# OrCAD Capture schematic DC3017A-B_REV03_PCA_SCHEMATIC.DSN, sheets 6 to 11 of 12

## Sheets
6 PORTS 9-12: size Custom
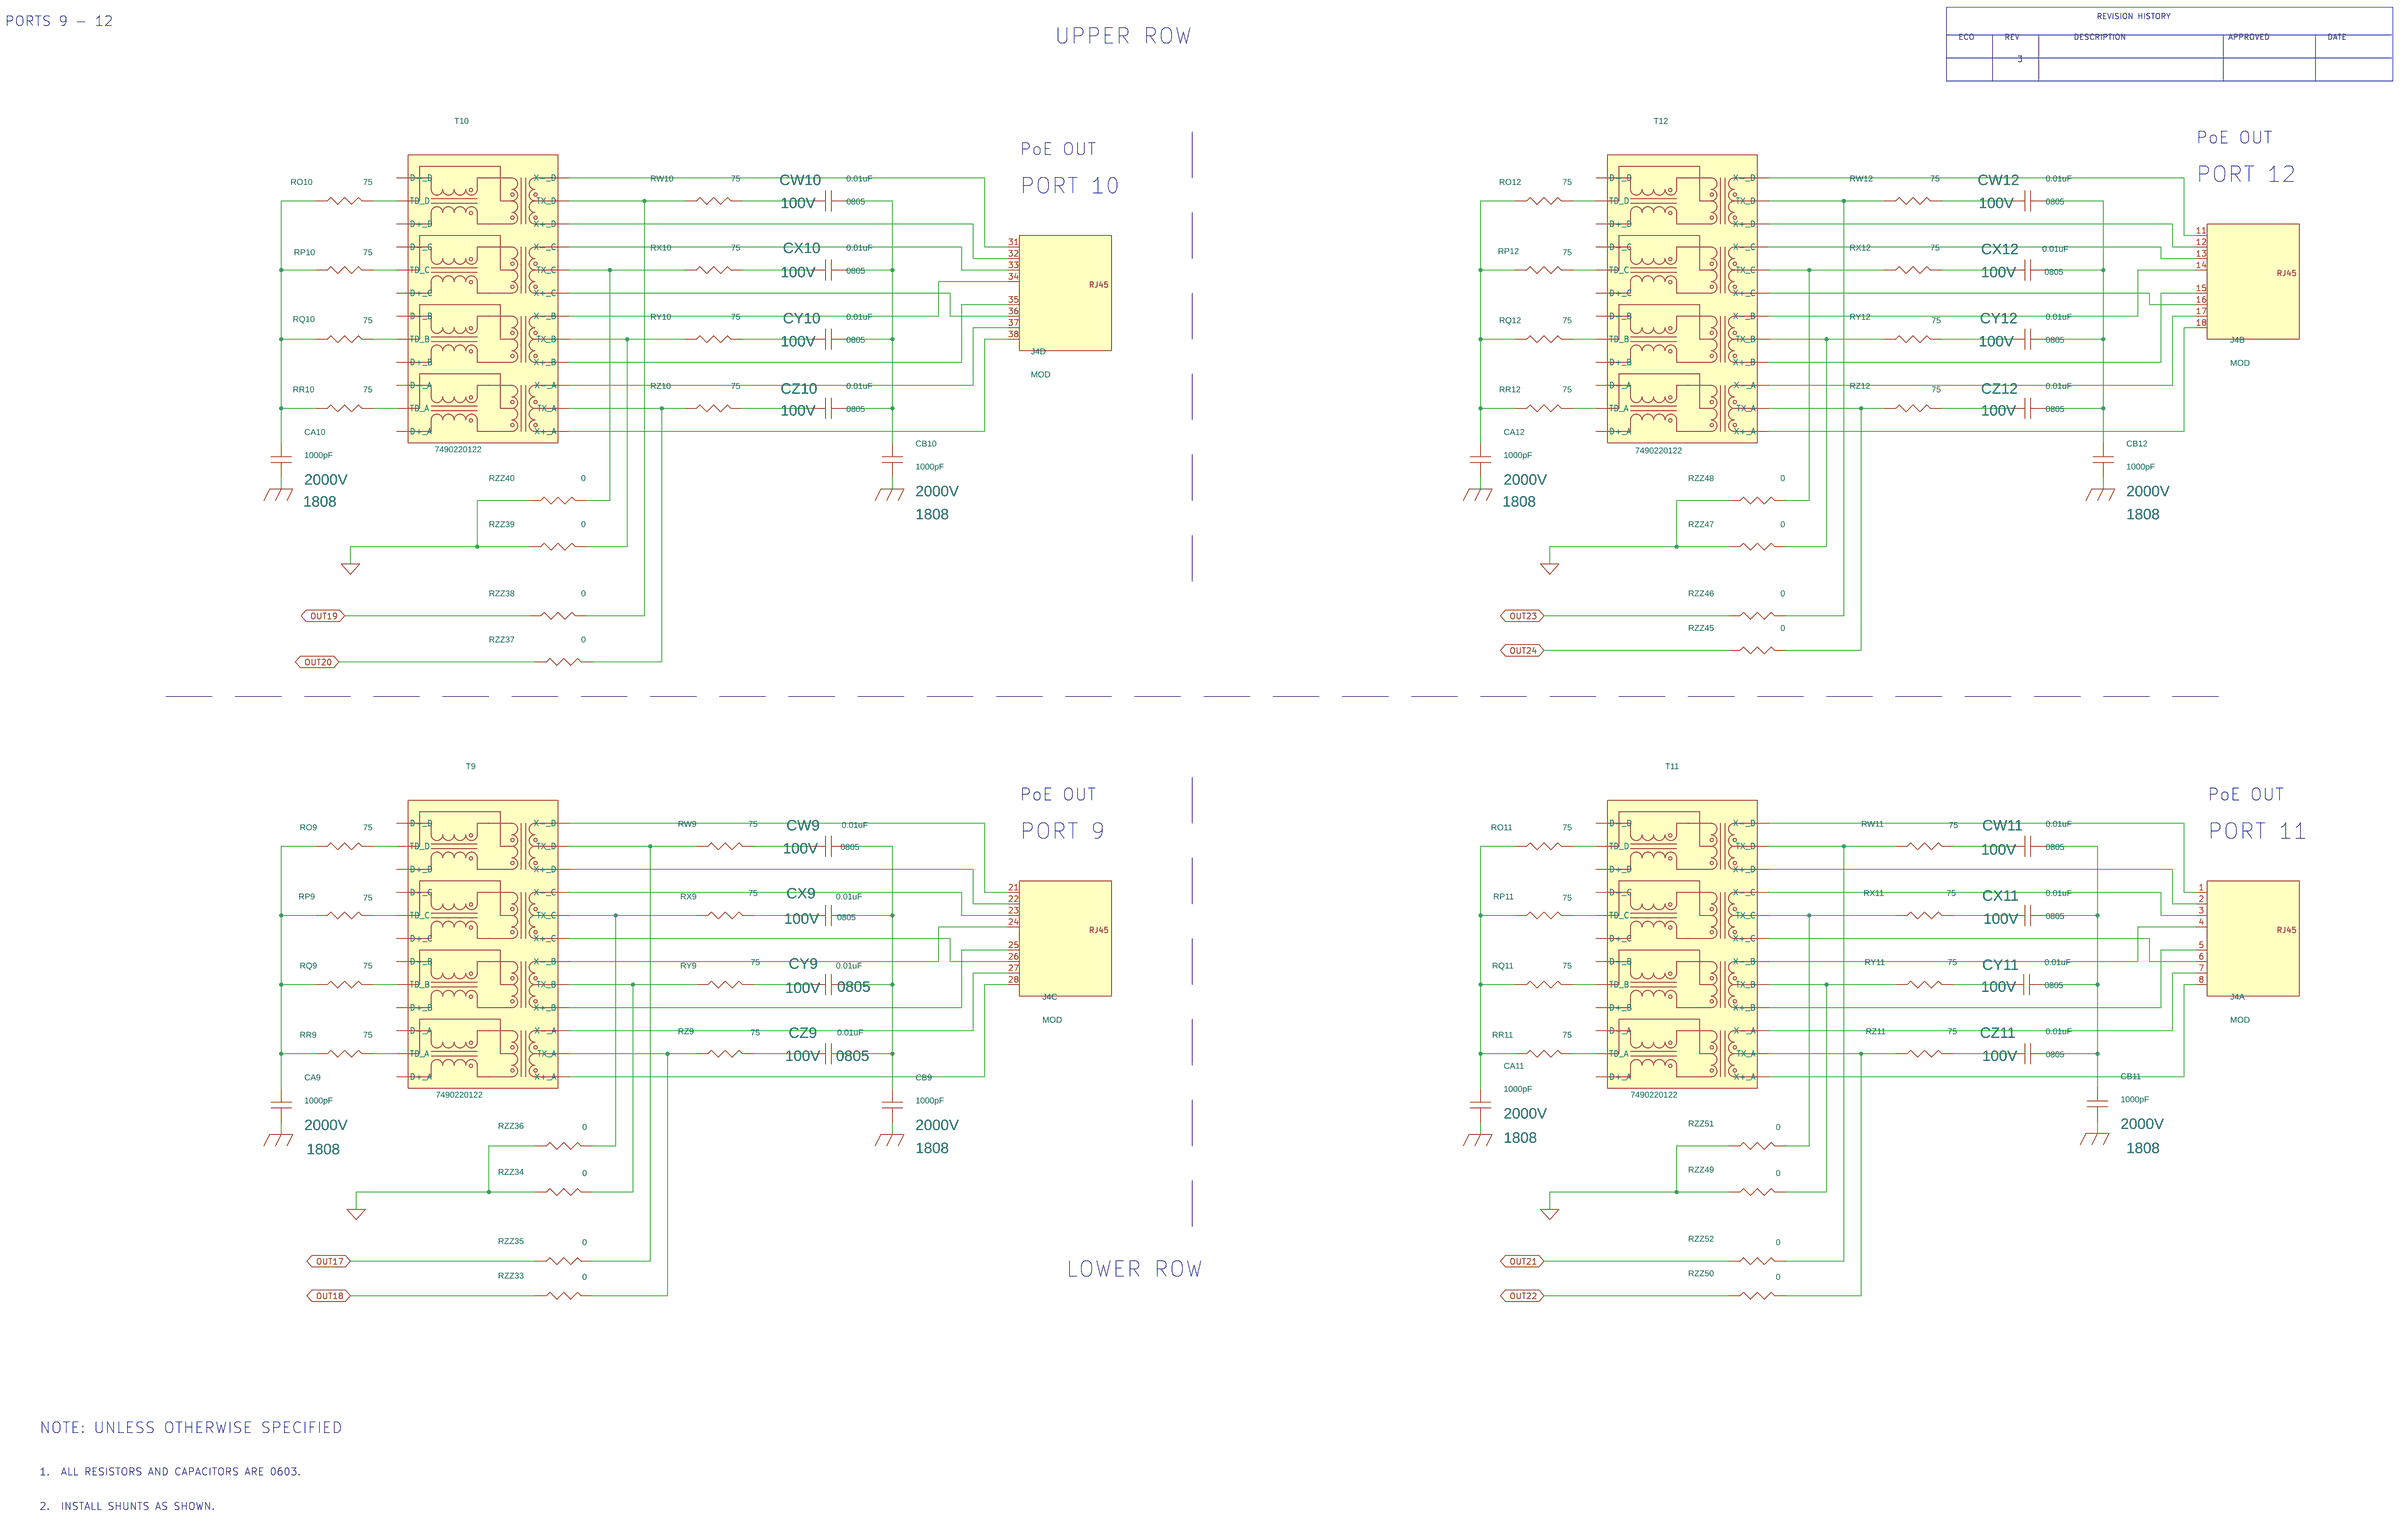
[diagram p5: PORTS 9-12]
7 PORTS 13-16: size Custom
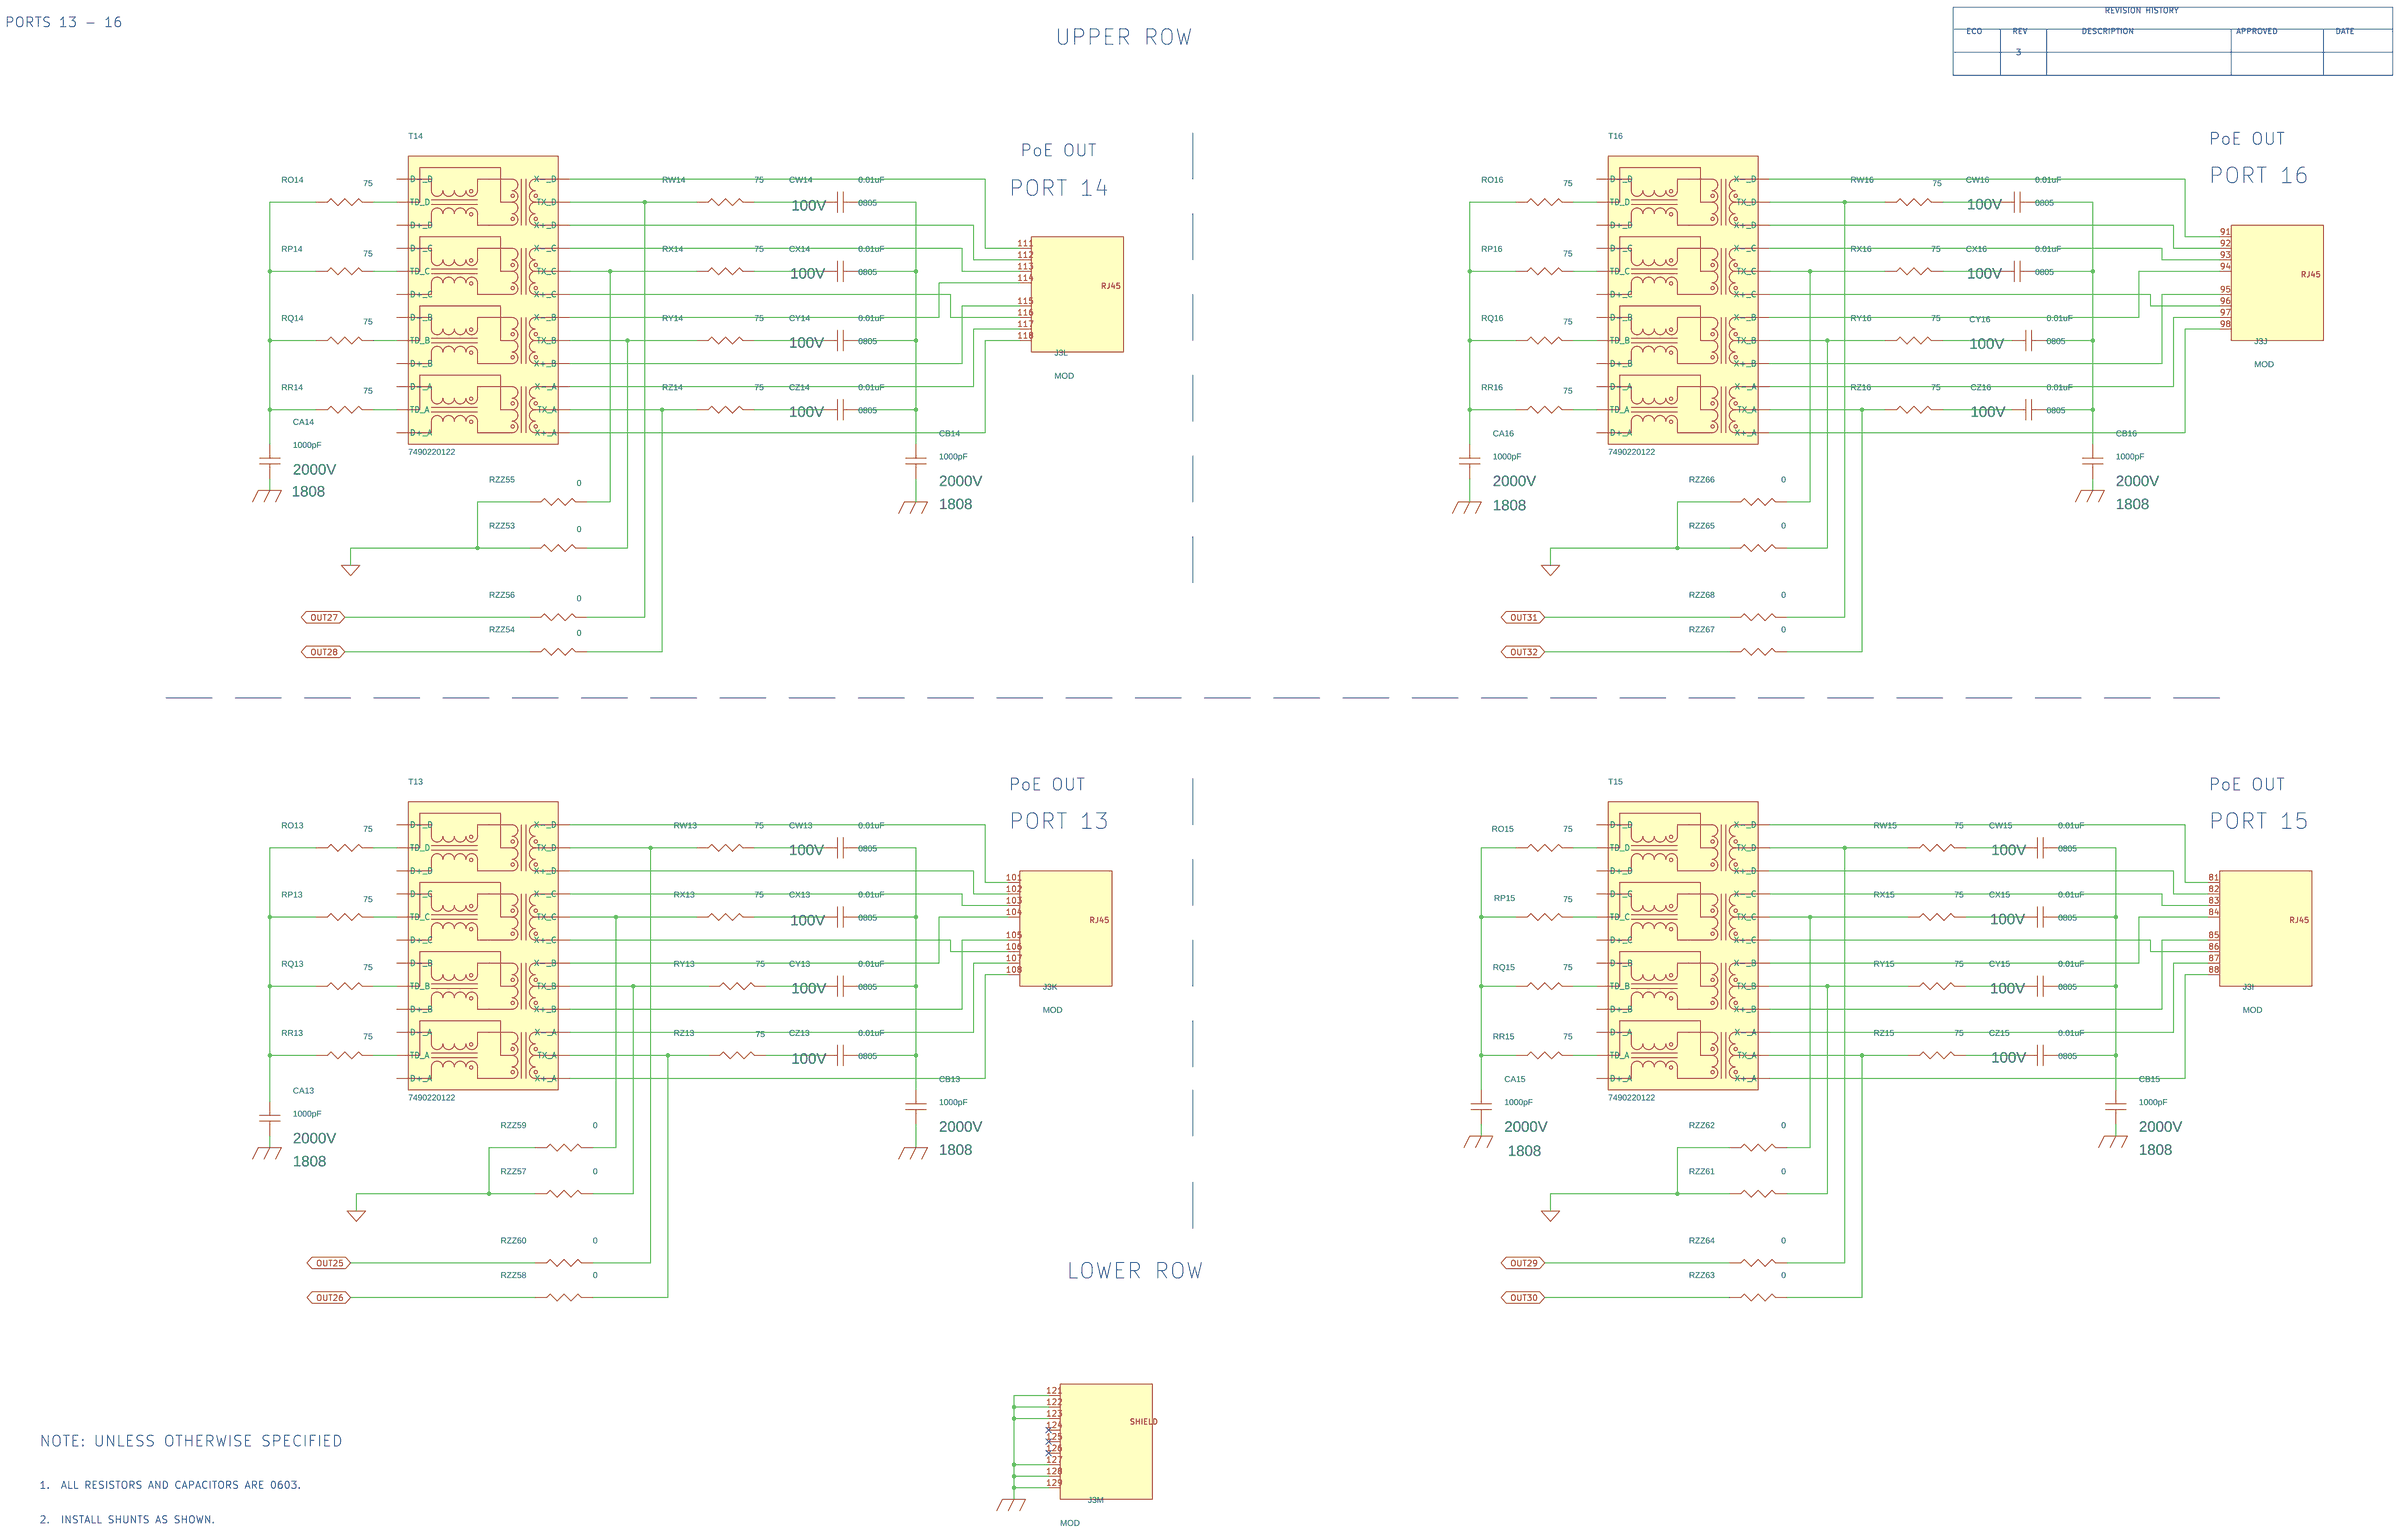
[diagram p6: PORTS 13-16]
8 PORTS 17-20: size Custom
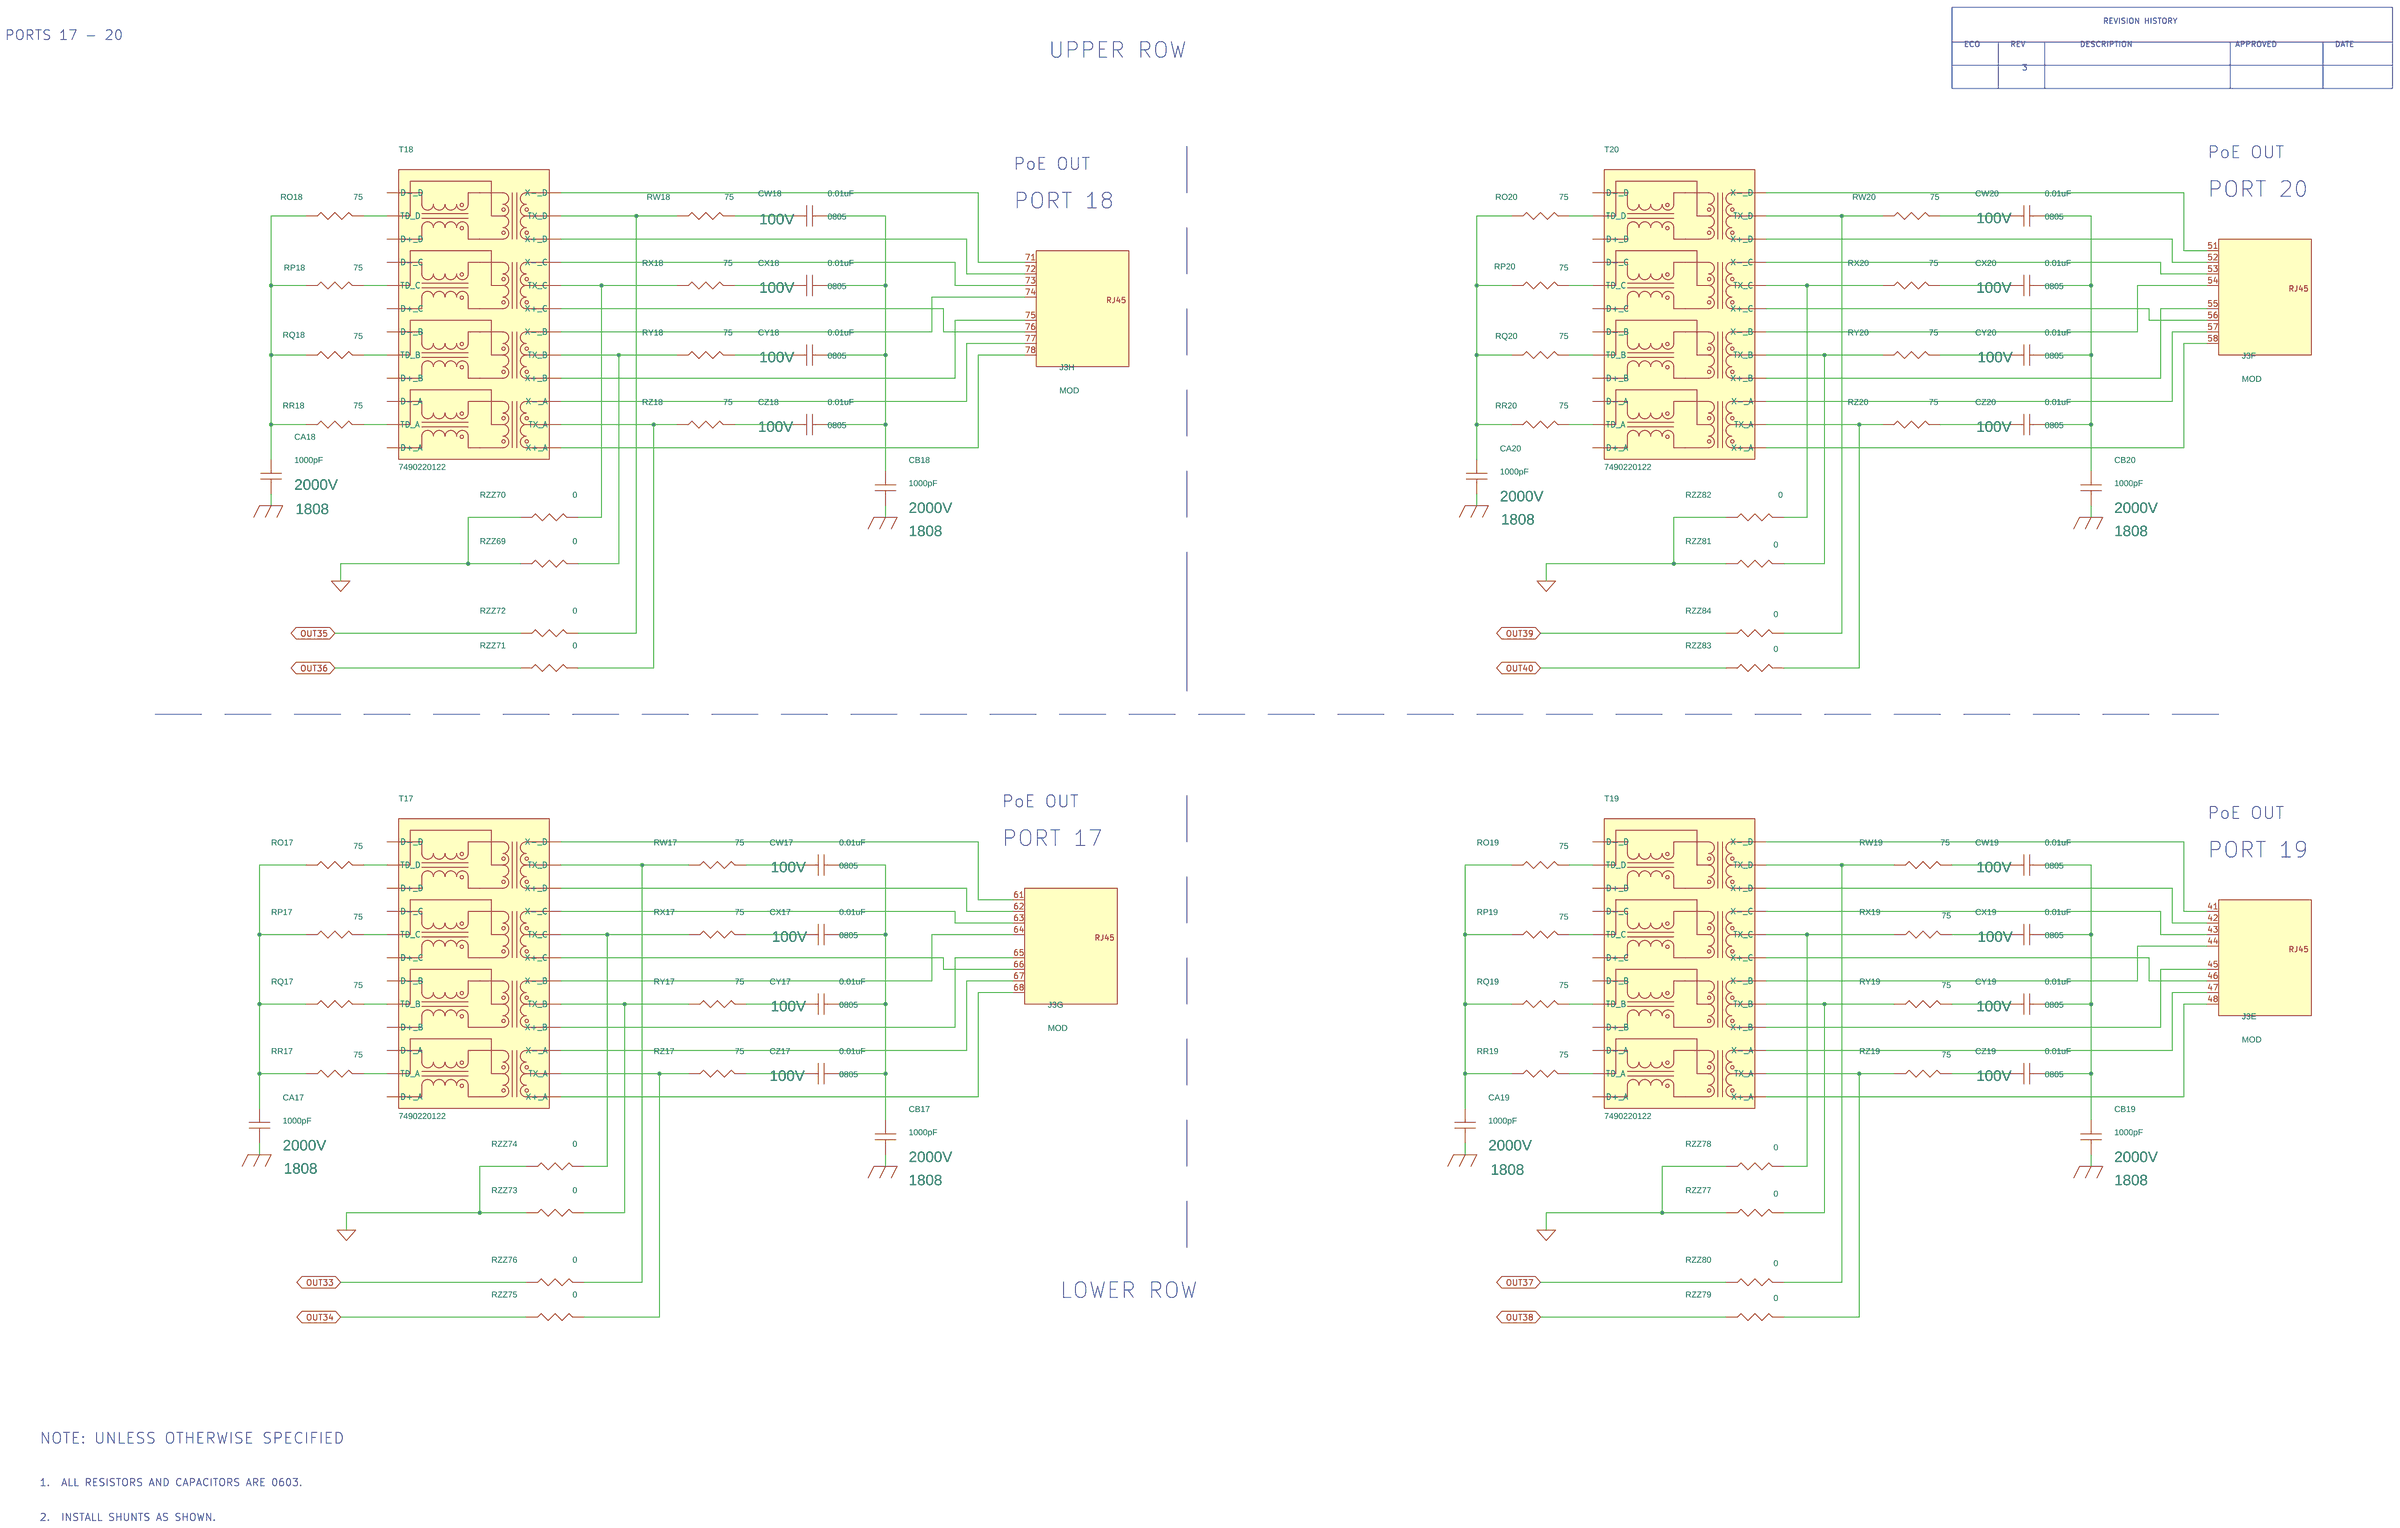
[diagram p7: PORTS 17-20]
9 PORTS 21-24: size Custom
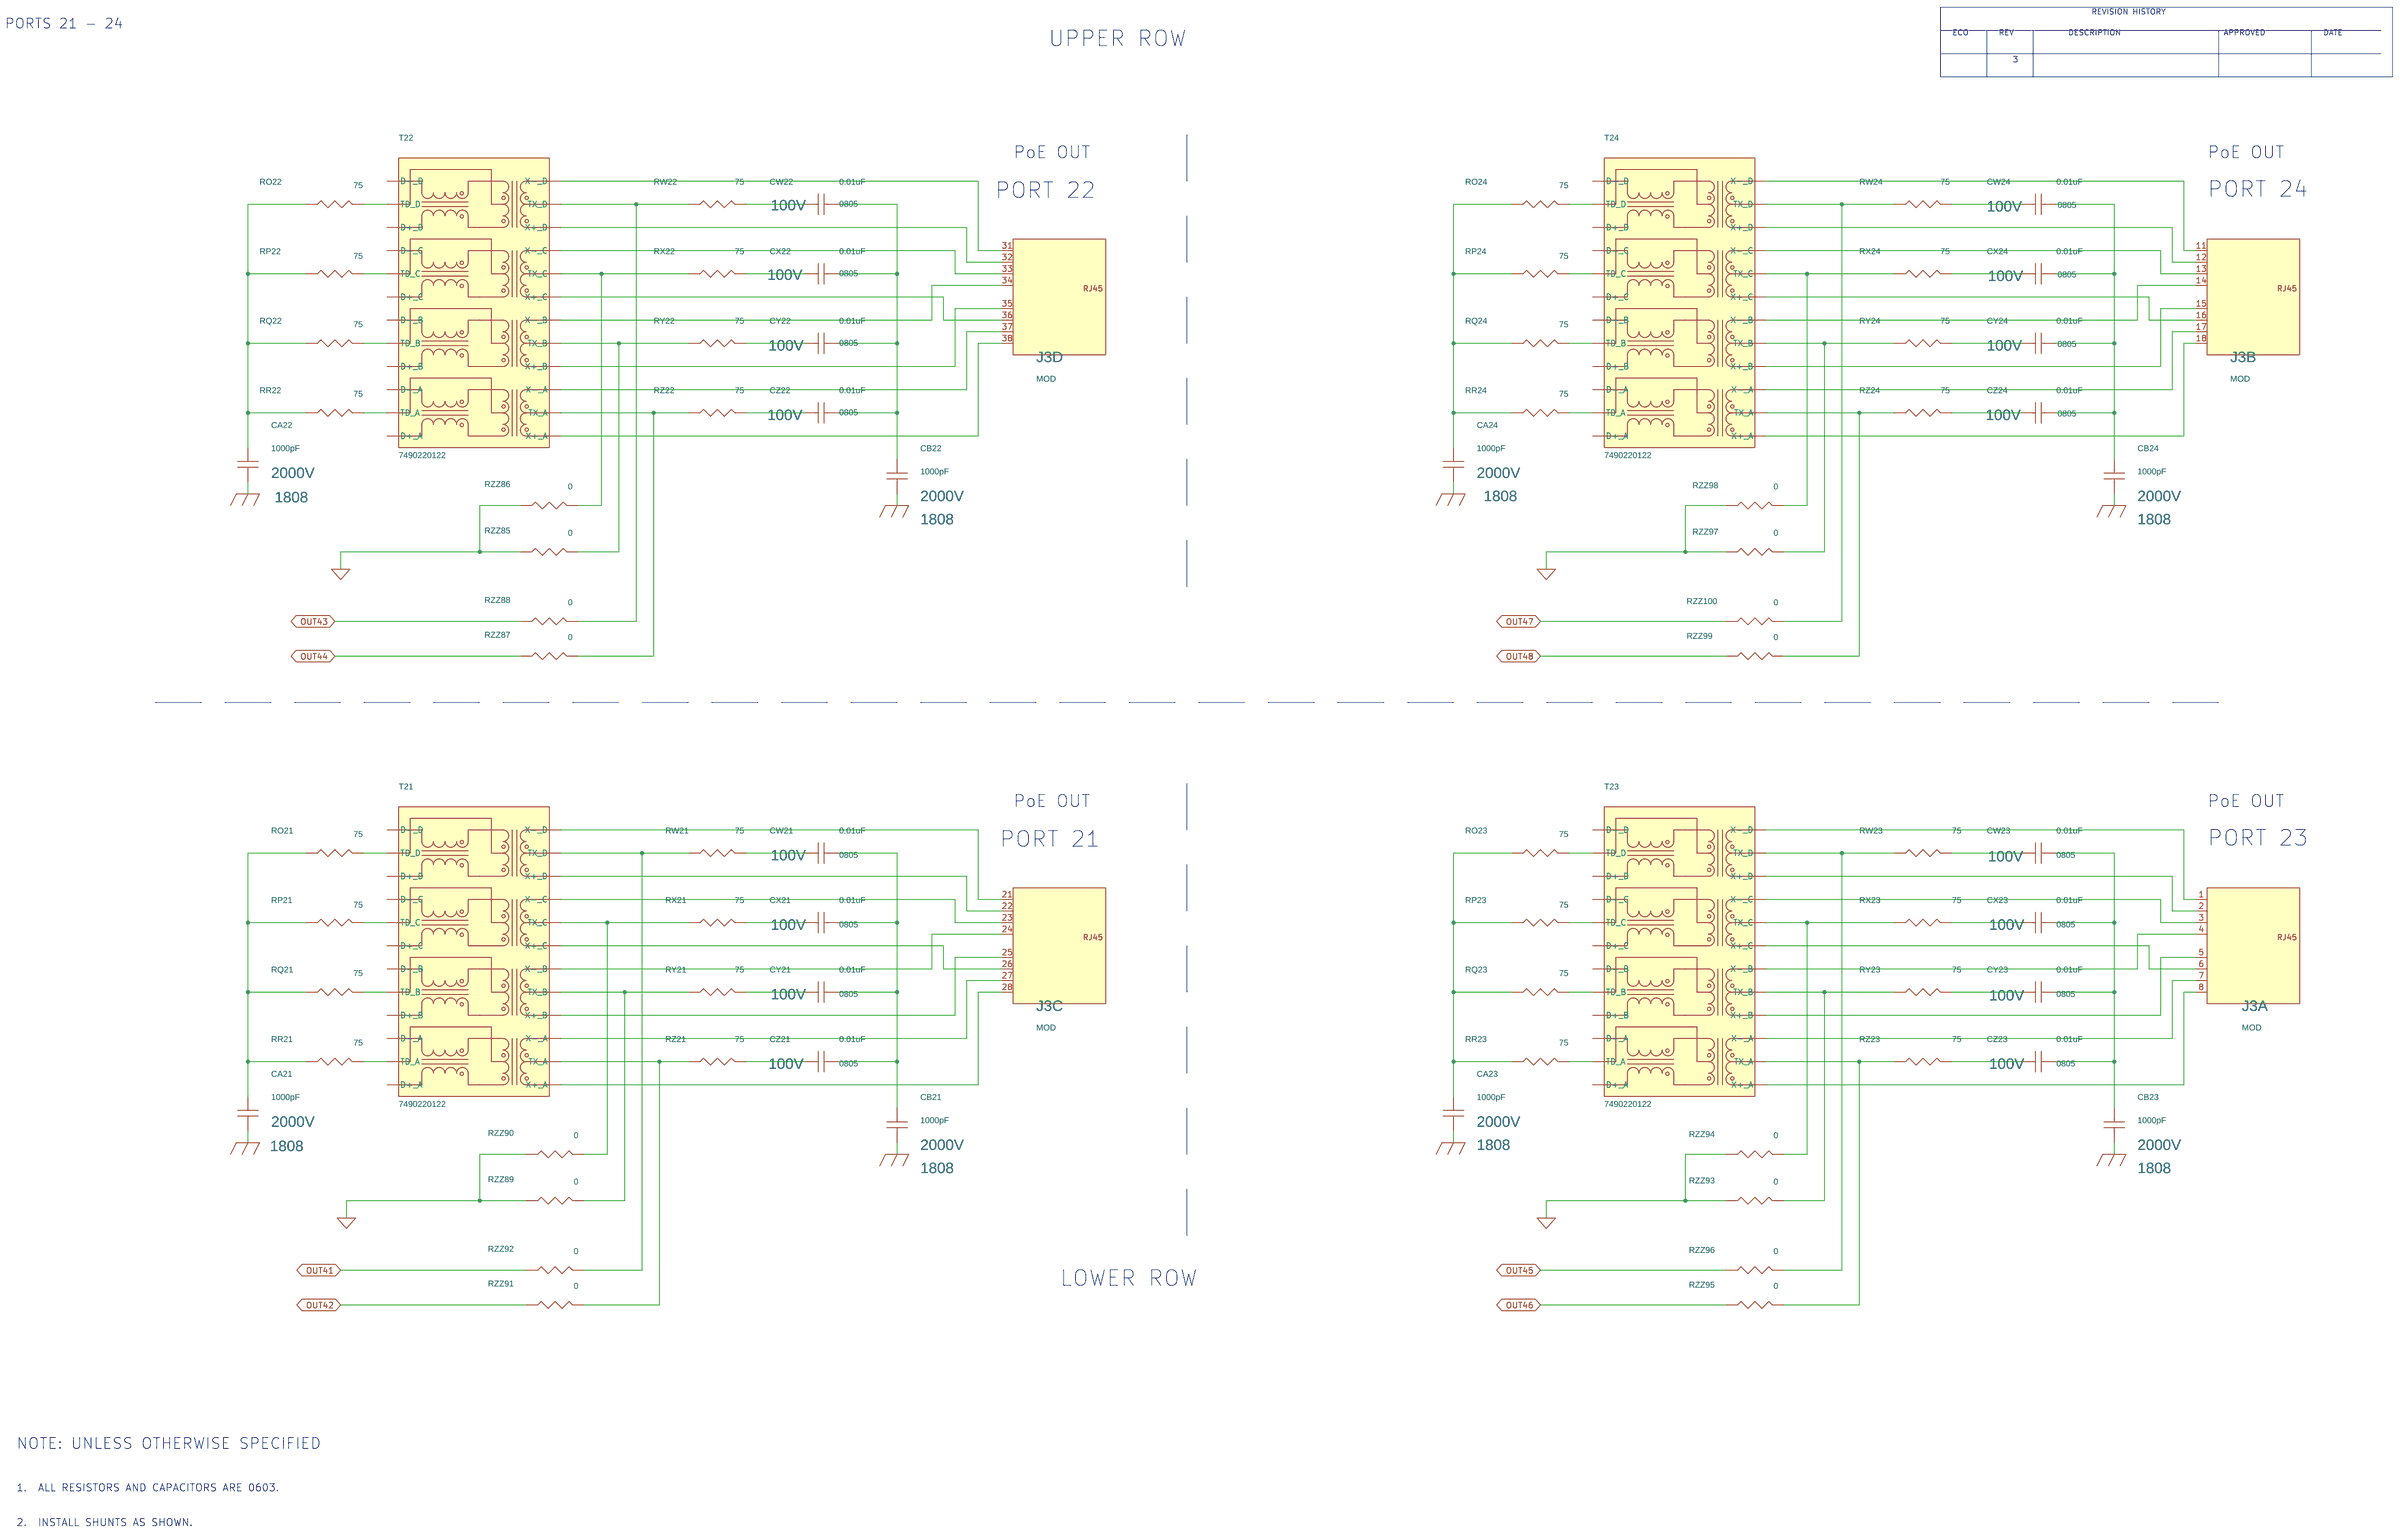
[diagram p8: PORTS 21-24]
10 _12-HARDWARE
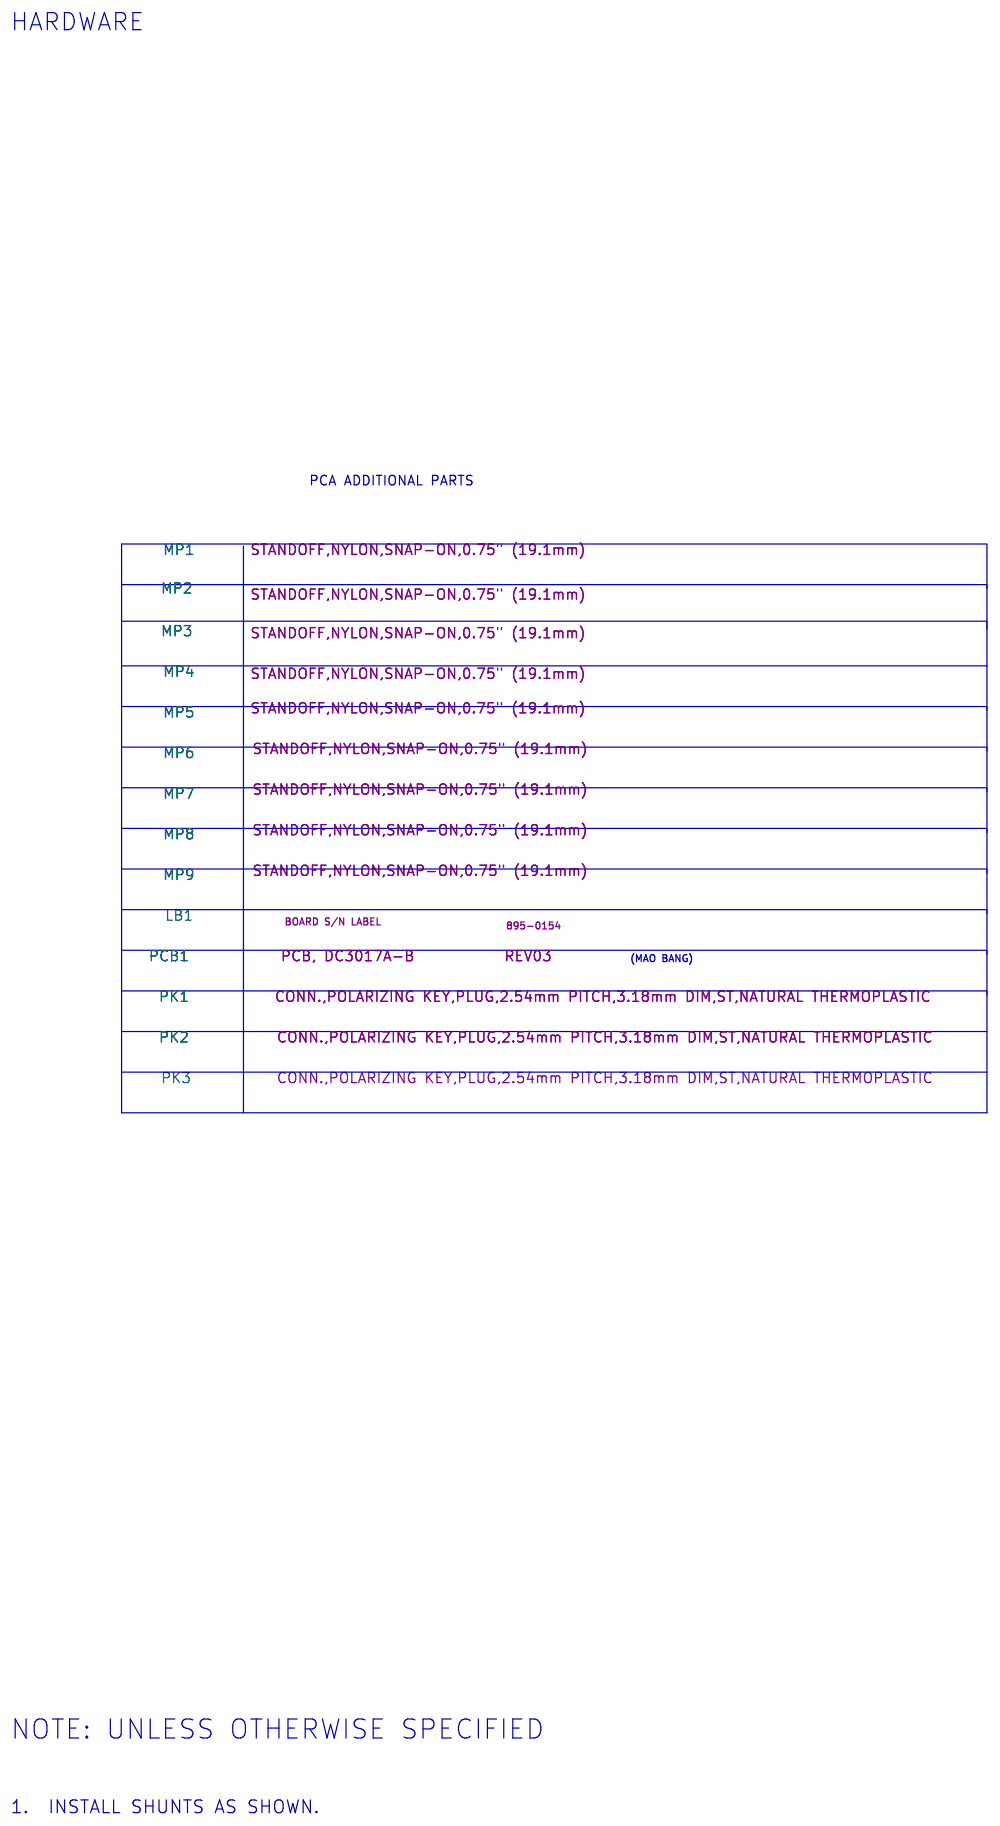
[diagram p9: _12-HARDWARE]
11 _11-PORTS 13-24 LEDS: size Custom
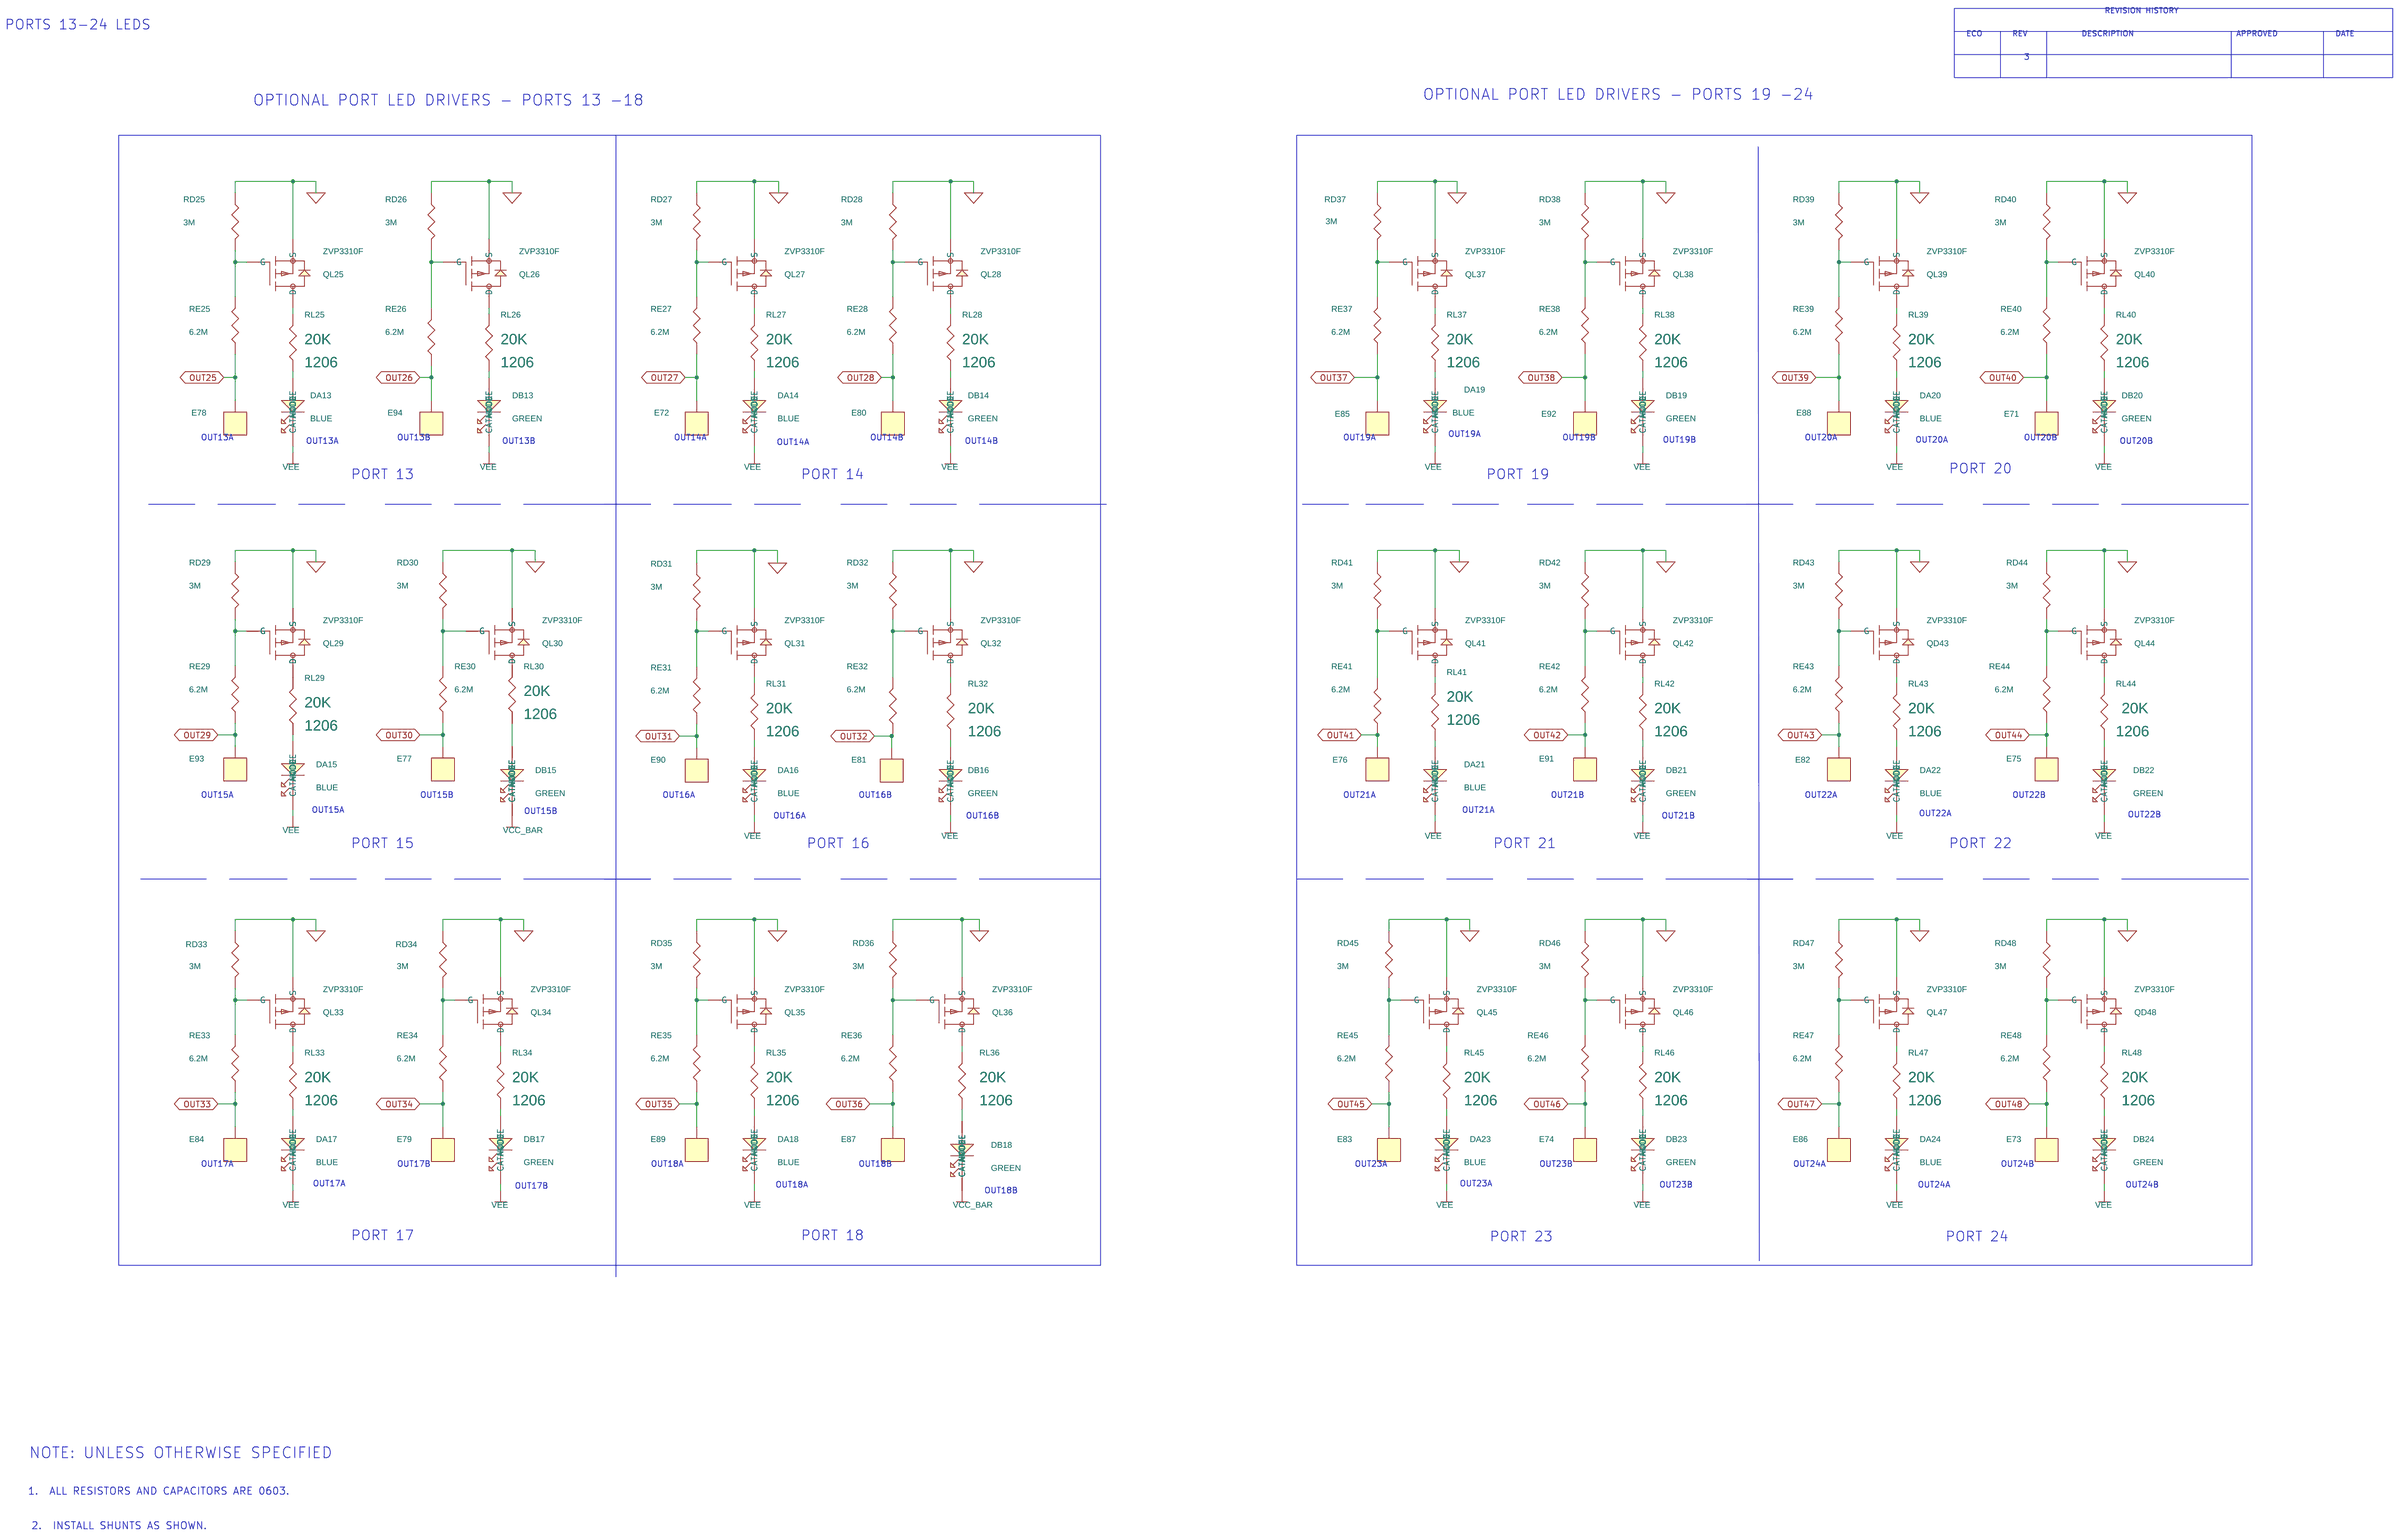
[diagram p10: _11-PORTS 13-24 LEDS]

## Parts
sheet _11-PORTS 13-24 LEDS
DA13  BLUE  [LED_0603]
DA14  BLUE  [LED_0603]
DA15  BLUE  [LED_0603]
DA16  BLUE  [LED_0603]
DA17  BLUE  [LED_0603]
DA18  BLUE  [LED_0603]
DA19  BLUE  [LED_0603]
DA20  BLUE  [LED_0603]
DA21  BLUE  [LED_0603]
DA22  BLUE  [LED_0603]
DA23  BLUE  [LED_0603]
DA24  BLUE  [LED_0603]
DB13  GREEN  [LED_0603]
DB14  GREEN  [LED_0603]
DB15  GREEN  [LED_0603]
DB16  GREEN  [LED_0603]
DB17  GREEN  [LED_0603]
DB18  GREEN  [LED_0603]
DB19  GREEN  [LED_0603]
DB20  GREEN  [LED_0603]
DB21  GREEN  [LED_0603]
DB22  GREEN  [LED_0603]
DB23  GREEN  [LED_0603]
DB24  GREEN  [LED_0603]
E71  TEST POINT  [KEYSTONE_5019]
E72  TEST POINT  [KEYSTONE_5019]
E73  TEST POINT  [KEYSTONE_5019]
E74  TEST POINT  [KEYSTONE_5019]
E75  TEST POINT  [KEYSTONE_5019]
E76  TEST POINT  [KEYSTONE_5019]
E77  TEST POINT  [KEYSTONE_5019]
E78  TEST POINT  [KEYSTONE_5019]
E79  TEST POINT  [KEYSTONE_5019]
E80  TEST POINT  [KEYSTONE_5019]
E81  TEST POINT  [KEYSTONE_5019]
E82  TEST POINT  [KEYSTONE_5019]
E83  TEST POINT  [KEYSTONE_5019]
E84  TEST POINT  [KEYSTONE_5019]
E85  TEST POINT  [KEYSTONE_5019]
E86  TEST POINT  [KEYSTONE_5019]
E87  TEST POINT  [KEYSTONE_5019]
E88  TEST POINT  [KEYSTONE_5019]
E89  TEST POINT  [KEYSTONE_5019]
E90  TEST POINT  [KEYSTONE_5019]
E91  TEST POINT  [KEYSTONE_5019]
E92  TEST POINT  [KEYSTONE_5019]
E93  TEST POINT  [KEYSTONE_5019]
E94  TEST POINT  [KEYSTONE_5019]
QD43  ZVP3310F  [SOT23-3N]
QD48  ZVP3310F  [SOT23-3N]
QL25  ZVP3310F  [SOT23-3N]
QL26  ZVP3310F  [SOT23-3N]
QL27  ZVP3310F  [SOT23-3N]
QL28  ZVP3310F  [SOT23-3N]
QL29  ZVP3310F  [SOT23-3N]
QL30  ZVP3310F  [SOT23-3N]
QL31  ZVP3310F  [SOT23-3N]
QL32  ZVP3310F  [SOT23-3N]
QL33  ZVP3310F  [SOT23-3N]
QL34  ZVP3310F  [SOT23-3N]
QL35  ZVP3310F  [SOT23-3N]
QL36  ZVP3310F  [SOT23-3N]
QL37  ZVP3310F  [SOT23-3N]
QL38  ZVP3310F  [SOT23-3N]
QL39  ZVP3310F  [SOT23-3N]
QL40  ZVP3310F  [SOT23-3N]
QL41  ZVP3310F  [SOT23-3N]
QL42  ZVP3310F  [SOT23-3N]
QL44  ZVP3310F  [SOT23-3N]
QL45  ZVP3310F  [SOT23-3N]
QL46  ZVP3310F  [SOT23-3N]
QL47  ZVP3310F  [SOT23-3N]
RD25  3M  [CR0603N]
RD26  3M  [CR0603N]
RD27  3M  [CR0603N]
RD28  3M  [CR0603N]
RD29  3M  [CR0603N]
RD30  3M  [CR0603N]
RD31  3M  [CR0603N]
RD32  3M  [CR0603N]
RD33  3M  [CR0603N]
RD34  3M  [CR0603N]
RD35  3M  [CR0603N]
RD36  3M  [CR0603N]
RD37  3M  [CR0603N]
RD38  3M  [CR0603N]
RD39  3M  [CR0603N]
RD40  3M  [CR0603N]
RD41  3M  [CR0603N]
RD42  3M  [CR0603N]
RD43  3M  [CR0603N]
RD44  3M  [CR0603N]
RD45  3M  [CR0603N]
RD46  3M  [CR0603N]
RD47  3M  [CR0603N]
RD48  3M  [CR0603N]
RE25  6.2M  [CR0603N]
RE26  6.2M  [CR0603N]
RE27  6.2M  [CR0603N]
RE28  6.2M  [CR0603N]
RE29  6.2M  [CR0603N]
RE30  6.2M  [CR0603N]
RE31  6.2M  [CR0603N]
RE32  6.2M  [CR0603N]
RE33  6.2M  [CR0603N]
RE34  6.2M  [CR0603N]
RE35  6.2M  [CR0603N]
RE36  6.2M  [CR0603N]
RE37  6.2M  [CR0603N]
RE38  6.2M  [CR0603N]
RE39  6.2M  [CR0603N]
RE40  6.2M  [CR0603N]
RE41  6.2M  [CR0603N]
RE42  6.2M  [CR0603N]
RE43  6.2M  [CR0603N]
RE44  6.2M  [CR0603N]
RE45  6.2M  [CR0603N]
RE46  6.2M  [CR0603N]
RE47  6.2M  [CR0603N]
RE48  6.2M  [CR0603N]
RL25  20K  [CR1206N]
RL26  20K  [CR1206N]
RL27  20K  [CR1206N]
RL28  20K  [CR1206N]
RL29  20K  [CR1206N]
RL30  20K  [CR1206N]
RL31  20K  [CR1206N]
RL32  20K  [CR1206N]
RL33  20K  [CR1206N]
RL34  20K  [CR1206N]
RL35  20K  [CR1206N]
RL36  20K  [CR1206N]
RL37  20K  [CR1206N]
RL38  20K  [CR1206N]
RL39  20K  [CR1206N]
RL40  20K  [CR1206N]
RL41  20K  [CR1206N]
RL42  20K  [CR1206N]
RL43  20K  [CR1206N]
RL44  20K  [CR1206N]
RL45  20K  [CR1206N]
RL46  20K  [CR1206N]
RL47  20K  [CR1206N]
RL48  20K  [CR1206N]
sheet _12-HARDWARE
LB1  LABEL  [895-0154_REV01]
MP1  STANDOFF  [KEYSTONE_8829-8834]
MP2  STANDOFF  [KEYSTONE_8829-8834]
MP3  STANDOFF  [KEYSTONE_8829-8834]
MP4  STANDOFF  [KEYSTONE_8829-8834]
MP5  STANDOFF  [KEYSTONE_8829-8834]
MP6  STANDOFF  [KEYSTONE_8829-8834]
MP7  STANDOFF  [KEYSTONE_8829-8834]
MP8  STANDOFF  [KEYSTONE_8829-8834]
MP9  STANDOFF  [KEYSTONE_8829-8834]
PCB1  PCB, DC3017A-B
PK1  POLARIZING KEY  [SAMTEC-PK-01-07]
PK2  POLARIZING KEY  [SAMTEC-PK-01-07]
PK3  POLARIZING KEY  [SAMTEC-PK-01-07]
sheet PORTS 1-4
J4  MOD  [STEWART-SS73100-046F]  (sections A,B,C,D,E,F,G,H,I,J,K,L,M)
sheet PORTS 9-12
CA9  1000pF  [CC1808N]
CA10  1000pF  [CC1808N]
CA11  1000pF  [CC1808N]
CA12  1000pF  [CC1808N]
CB9  1000pF  [CC1808N]
CB10  1000pF  [CC1808N]
CB11  1000pF  [CC1808N]
CB12  1000pF  [CC1808N]
CW9  0.01uF  [CC0805N]
CW10  0.01uF  [CC0805N]
CW11  0.01uF  [CC0805N]
CW12  0.01uF  [CC0805N]
CX9  0.01uF  [CC0805N]
CX10  0.01uF  [CC0805N]
CX11  0.01uF  [CC0805N]
CX12  0.01uF  [CC0805N]
CY9  0.01uF  [CC0805N]
CY10  0.01uF  [CC0805N]
CY11  0.01uF  [CC0805N]
CY12  0.01uF  [CC0805N]
CZ9  0.01uF  [CC0805N]
CZ10  0.01uF  [CC0805N]
CZ11  0.01uF  [CC0805N]
CZ12  0.01uF  [CC0805N]
RO9  75  [CR0603N]
RO10  75  [CR0603N]
RO11  75  [CR0603N]
RO12  75  [CR0603N]
RP9  75  [CR0603N]
RP10  75  [CR0603N]
RP11  75  [CR0603N]
RP12  75  [CR0603N]
RQ9  75  [CR0603N]
RQ10  75  [CR0603N]
RQ11  75  [CR0603N]
RQ12  75  [CR0603N]
RR9  75  [CR0603N]
RR10  75  [CR0603N]
RR11  75  [CR0603N]
RR12  75  [CR0603N]
RW9  75  [CR0603N]
RW10  75  [CR0603N]
RW11  75  [CR0603N]
RW12  75  [CR0603N]
RX9  75  [CR0603N]
RX10  75  [CR0603N]
RX11  75  [CR0603N]
RX12  75  [CR0603N]
RY9  75  [CR0603N]
RY10  75  [CR0603N]
RY11  75  [CR0603N]
RY12  75  [CR0603N]
RZ9  75  [CR0603N]
RZ10  75  [CR0603N]
RZ11  75  [CR0603N]
RZ12  75  [CR0603N]
RZZ33  0  [CR0603N]
RZZ34  0  [CR0603N]
RZZ35  0  [CR0603N]
RZZ36  0  [CR0603N]
RZZ37  0  [CR0603N]
RZZ38  0  [CR0603N]
RZZ39  0  [CR0603N]
RZZ40  0  [CR0603N]
RZZ45  0  [CR0603N]
RZZ46  0  [CR0603N]
RZZ47  0  [CR0603N]
RZZ48  0  [CR0603N]
RZZ49  0  [CR0603N]
RZZ50  0  [CR0603N]
RZZ51  0  [CR0603N]
RZZ52  0  [CR0603N]
T9  7490220122  [WURTH-7490220122]
T10  7490220122  [WURTH-7490220122]
T11  7490220122  [WURTH-7490220122]
T12  7490220122  [WURTH-7490220122]
sheet PORTS 13-16
CA13  1000pF  [CC1808N]
CA14  1000pF  [CC1808N]
CA15  1000pF  [CC1808N]
CA16  1000pF  [CC1808N]
CB13  1000pF  [CC1808N]
CB14  1000pF  [CC1808N]
CB15  1000pF  [CC1808N]
CB16  1000pF  [CC1808N]
CW13  0.01uF  [CC0805N]
CW14  0.01uF  [CC0805N]
CW15  0.01uF  [CC0805N]
CW16  0.01uF  [CC0805N]
CX13  0.01uF  [CC0805N]
CX14  0.01uF  [CC0805N]
CX15  0.01uF  [CC0805N]
CX16  0.01uF  [CC0805N]
CY13  0.01uF  [CC0805N]
CY14  0.01uF  [CC0805N]
CY15  0.01uF  [CC0805N]
CY16  0.01uF  [CC0805N]
CZ13  0.01uF  [CC0805N]
CZ14  0.01uF  [CC0805N]
CZ15  0.01uF  [CC0805N]
CZ16  0.01uF  [CC0805N]
RO13  75  [CR0603N]
RO14  75  [CR0603N]
RO15  75  [CR0603N]
RO16  75  [CR0603N]
RP13  75  [CR0603N]
RP14  75  [CR0603N]
RP15  75  [CR0603N]
RP16  75  [CR0603N]
RQ13  75  [CR0603N]
RQ14  75  [CR0603N]
RQ15  75  [CR0603N]
RQ16  75  [CR0603N]
RR13  75  [CR0603N]
RR14  75  [CR0603N]
RR15  75  [CR0603N]
RR16  75  [CR0603N]
RW13  75  [CR0603N]
RW14  75  [CR0603N]
RW15  75  [CR0603N]
RW16  75  [CR0603N]
RX13  75  [CR0603N]
RX14  75  [CR0603N]
RX15  75  [CR0603N]
RX16  75  [CR0603N]
RY13  75  [CR0603N]
RY14  75  [CR0603N]
RY15  75  [CR0603N]
RY16  75  [CR0603N]
RZ13  75  [CR0603N]
RZ14  75  [CR0603N]
RZ15  75  [CR0603N]
RZ16  75  [CR0603N]
RZZ53  0  [CR0603N]
RZZ54  0  [CR0603N]
RZZ55  0  [CR0603N]
RZZ56  0  [CR0603N]
RZZ57  0  [CR0603N]
RZZ58  0  [CR0603N]
RZZ59  0  [CR0603N]
RZZ60  0  [CR0603N]
RZZ61  0  [CR0603N]
RZZ62  0  [CR0603N]
RZZ63  0  [CR0603N]
RZZ64  0  [CR0603N]
RZZ65  0  [CR0603N]
RZZ66  0  [CR0603N]
RZZ67  0  [CR0603N]
RZZ68  0  [CR0603N]
T13  7490220122  [WURTH-7490220122]
T14  7490220122  [WURTH-7490220122]
T15  7490220122  [WURTH-7490220122]
T16  7490220122  [WURTH-7490220122]
sheet PORTS 17-20
CA17  1000pF  [CC1808N]
CA18  1000pF  [CC1808N]
CA19  1000pF  [CC1808N]
CA20  1000pF  [CC1808N]
CB17  1000pF  [CC1808N]
CB18  1000pF  [CC1808N]
CB19  1000pF  [CC1808N]
CB20  1000pF  [CC1808N]
CW17  0.01uF  [CC0805N]
CW18  0.01uF  [CC0805N]
CW19  0.01uF  [CC0805N]
CW20  0.01uF  [CC0805N]
CX17  0.01uF  [CC0805N]
CX18  0.01uF  [CC0805N]
CX19  0.01uF  [CC0805N]
CX20  0.01uF  [CC0805N]
CY17  0.01uF  [CC0805N]
CY18  0.01uF  [CC0805N]
CY19  0.01uF  [CC0805N]
CY20  0.01uF  [CC0805N]
CZ17  0.01uF  [CC0805N]
CZ18  0.01uF  [CC0805N]
CZ19  0.01uF  [CC0805N]
CZ20  0.01uF  [CC0805N]
J3  MOD  [STEWART-SS73100-046F]  (sections A,B,C,D,E,F,G,H,I,J,K,L,M)
RO17  75  [CR0603N]
RO18  75  [CR0603N]
RO19  75  [CR0603N]
RO20  75  [CR0603N]
RP17  75  [CR0603N]
RP18  75  [CR0603N]
RP19  75  [CR0603N]
RP20  75  [CR0603N]
RQ17  75  [CR0603N]
RQ18  75  [CR0603N]
RQ19  75  [CR0603N]
RQ20  75  [CR0603N]
RR17  75  [CR0603N]
RR18  75  [CR0603N]
RR19  75  [CR0603N]
RR20  75  [CR0603N]
RW17  75  [CR0603N]
RW18  75  [CR0603N]
RW19  75  [CR0603N]
RW20  75  [CR0603N]
RX17  75  [CR0603N]
RX18  75  [CR0603N]
RX19  75  [CR0603N]
RX20  75  [CR0603N]
RY17  75  [CR0603N]
RY18  75  [CR0603N]
RY19  75  [CR0603N]
RY20  75  [CR0603N]
RZ17  75  [CR0603N]
RZ18  75  [CR0603N]
RZ19  75  [CR0603N]
RZ20  75  [CR0603N]
RZZ69  0  [CR0603N]
RZZ70  0  [CR0603N]
RZZ71  0  [CR0603N]
RZZ72  0  [CR0603N]
RZZ73  0  [CR0603N]
RZZ74  0  [CR0603N]
RZZ75  0  [CR0603N]
RZZ76  0  [CR0603N]
RZZ77  0  [CR0603N]
RZZ78  0  [CR0603N]
RZZ79  0  [CR0603N]
RZZ80  0  [CR0603N]
RZZ81  0  [CR0603N]
RZZ82  0  [CR0603N]
RZZ83  0  [CR0603N]
RZZ84  0  [CR0603N]
T17  7490220122  [WURTH-7490220122]
T18  7490220122  [WURTH-7490220122]
T19  7490220122  [WURTH-7490220122]
T20  7490220122  [WURTH-7490220122]
sheet PORTS 21-24
CA21  1000pF  [CC1808N]
CA22  1000pF  [CC1808N]
CA23  1000pF  [CC1808N]
CA24  1000pF  [CC1808N]
CB21  1000pF  [CC1808N]
CB22  1000pF  [CC1808N]
CB23  1000pF  [CC1808N]
CB24  1000pF  [CC1808N]
CW21  0.01uF  [CC0805N]
CW22  0.01uF  [CC0805N]
CW23  0.01uF  [CC0805N]
CW24  0.01uF  [CC0805N]
CX21  0.01uF  [CC0805N]
CX22  0.01uF  [CC0805N]
CX23  0.01uF  [CC0805N]
CX24  0.01uF  [CC0805N]
CY21  0.01uF  [CC0805N]
CY22  0.01uF  [CC0805N]
CY23  0.01uF  [CC0805N]
CY24  0.01uF  [CC0805N]
CZ21  0.01uF  [CC0805N]
CZ22  0.01uF  [CC0805N]
CZ23  0.01uF  [CC0805N]
CZ24  0.01uF  [CC0805N]
RO21  75  [CR0603N]
RO22  75  [CR0603N]
RO23  75  [CR0603N]
RO24  75  [CR0603N]
RP21  75  [CR0603N]
RP22  75  [CR0603N]
RP23  75  [CR0603N]
RP24  75  [CR0603N]
RQ21  75  [CR0603N]
RQ22  75  [CR0603N]
RQ23  75  [CR0603N]
RQ24  75  [CR0603N]
RR21  75  [CR0603N]
RR22  75  [CR0603N]
RR23  75  [CR0603N]
RR24  75  [CR0603N]
RW21  75  [CR0603N]
RW22  75  [CR0603N]
RW23  75  [CR0603N]
RW24  75  [CR0603N]
RX21  75  [CR0603N]
RX22  75  [CR0603N]
RX23  75  [CR0603N]
RX24  75  [CR0603N]
RY21  75  [CR0603N]
RY22  75  [CR0603N]
RY23  75  [CR0603N]
RY24  75  [CR0603N]
RZ21  75  [CR0603N]
RZ22  75  [CR0603N]
RZ23  75  [CR0603N]
RZ24  75  [CR0603N]
RZZ85  0  [CR0603N]
RZZ86  0  [CR0603N]
RZZ87  0  [CR0603N]
RZZ88  0  [CR0603N]
RZZ89  0  [CR0603N]
RZZ90  0  [CR0603N]
RZZ91  0  [CR0603N]
RZZ92  0  [CR0603N]
RZZ93  0  [CR0603N]
RZZ94  0  [CR0603N]
RZZ95  0  [CR0603N]
RZZ96  0  [CR0603N]
RZZ97  0  [CR0603N]
RZZ98  0  [CR0603N]
RZZ99  0  [CR0603N]
RZZ100  0  [CR0603N]
T21  7490220122  [WURTH-7490220122]
T22  7490220122  [WURTH-7490220122]
T23  7490220122  [WURTH-7490220122]
T24  7490220122  [WURTH-7490220122]

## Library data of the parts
DA13 = LED: LED,BLUE,WATER CLEAR,0603; 1ST PART FIELD: OUT13A; CLASS: DISCRETE; Inventory Qty: 0; LED: GREEN; Manufacturer: Wurth Elektronik; Manufacturer PN: 155060BS75300; PART_NUMBER: 270-0164; Package Type: 0603
DA14 = LED: LED,BLUE,WATER CLEAR,0603; 1ST PART FIELD: OUT14A; CLASS: DISCRETE; Inventory Qty: 0; LED: GREEN; Manufacturer: Wurth Elektronik; Manufacturer PN: 155060BS75300; PART_NUMBER: 270-0164; Package Type: 0603
DA15 = LED: LED,BLUE,WATER CLEAR,0603; 1ST PART FIELD: OUT15A; CLASS: DISCRETE; Inventory Qty: 0; LED: GREEN; Manufacturer: Wurth Elektronik; Manufacturer PN: 155060BS75300; PART_NUMBER: 270-0164; Package Type: 0603
DA16 = LED: LED,BLUE,WATER CLEAR,0603; 1ST PART FIELD: OUT16A; CLASS: DISCRETE; Inventory Qty: 0; LED: GREEN; Manufacturer: Wurth Elektronik; Manufacturer PN: 155060BS75300; PART_NUMBER: 270-0164; Package Type: 0603
DA17 = LED: LED,BLUE,WATER CLEAR,0603; 1ST PART FIELD: OUT17A; CLASS: DISCRETE; Inventory Qty: 0; LED: GREEN; Manufacturer: Wurth Elektronik; Manufacturer PN: 155060BS75300; PART_NUMBER: 270-0164; Package Type: 0603
DA18 = LED: LED,BLUE,WATER CLEAR,0603; 1ST PART FIELD: OUT18A; CLASS: DISCRETE; Inventory Qty: 0; LED: GREEN; Manufacturer: Wurth Elektronik; Manufacturer PN: 155060BS75300; PART_NUMBER: 270-0164; Package Type: 0603
DA19 = LED: LED,BLUE,WATER CLEAR,0603; 1ST PART FIELD: OUT19A; CLASS: DISCRETE; Inventory Qty: 0; LED: GREEN; Manufacturer: Wurth Elektronik; Manufacturer PN: 155060BS75300; PART_NUMBER: 270-0164; Package Type: 0603
DA20 = LED: LED,BLUE,WATER CLEAR,0603; 1ST PART FIELD: OUT20A; CLASS: DISCRETE; Inventory Qty: 0; LED: GREEN; Manufacturer: Wurth Elektronik; Manufacturer PN: 155060BS75300; PART_NUMBER: 270-0164; Package Type: 0603
DA21 = LED: LED,BLUE,WATER CLEAR,0603; 1ST PART FIELD: OUT21A; CLASS: DISCRETE; Inventory Qty: 0; LED: GREEN; Manufacturer: Wurth Elektronik; Manufacturer PN: 155060BS75300; PART_NUMBER: 270-0164; Package Type: 0603
DA22 = LED: LED,BLUE,WATER CLEAR,0603; 1ST PART FIELD: OUT22A; CLASS: DISCRETE; Inventory Qty: 0; LED: GREEN; Manufacturer: Wurth Elektronik; Manufacturer PN: 155060BS75300; PART_NUMBER: 270-0164; Package Type: 0603
DA23 = LED: LED,BLUE,WATER CLEAR,0603; 1ST PART FIELD: OUT23A; CLASS: DISCRETE; Inventory Qty: 0; LED: GREEN; Manufacturer: Wurth Elektronik; Manufacturer PN: 155060BS75300; PART_NUMBER: 270-0164; Package Type: 0603
DA24 = LED: LED,BLUE,WATER CLEAR,0603; 1ST PART FIELD: OUT24A; CLASS: DISCRETE; Inventory Qty: 0; LED: GREEN; Manufacturer: Wurth Elektronik; Manufacturer PN: 155060BS75300; PART_NUMBER: 270-0164; Package Type: 0603
DB13 = LED: LED,GREEN,DIFFUSED,0603; 1ST PART FIELD: OUT13B; CLASS: DISCRETE; Inventory Qty: 4424; LED: BLUE; Manufacturer: ROHM; Manufacturer PN: SML-E12P8WT86; PART_NUMBER: 270-0176; Package Type: 0603
DB14 = LED: LED,GREEN,DIFFUSED,0603; 1ST PART FIELD: OUT14B; CLASS: DISCRETE; Inventory Qty: 4424; LED: BLUE; Manufacturer: ROHM; Manufacturer PN: SML-E12P8WT86; PART_NUMBER: 270-0176; Package Type: 0603
DB15 = LED: LED,GREEN,DIFFUSED,0603; 1ST PART FIELD: OUT15B; CLASS: DISCRETE; Inventory Qty: 4424; LED: BLUE; Manufacturer: ROHM; Manufacturer PN: SML-E12P8WT86; PART_NUMBER: 270-0176; Package Type: 0603
DB16 = LED: LED,GREEN,DIFFUSED,0603; 1ST PART FIELD: OUT16B; CLASS: DISCRETE; Inventory Qty: 4424; LED: BLUE; Manufacturer: ROHM; Manufacturer PN: SML-E12P8WT86; PART_NUMBER: 270-0176; Package Type: 0603
DB17 = LED: LED,GREEN,DIFFUSED,0603; 1ST PART FIELD: OUT17B; CLASS: DISCRETE; Inventory Qty: 4424; LED: BLUE; Manufacturer: ROHM; Manufacturer PN: SML-E12P8WT86; PART_NUMBER: 270-0176; Package Type: 0603
DB18 = LED: LED,GREEN,DIFFUSED,0603; 1ST PART FIELD: OUT18B; CLASS: DISCRETE; Inventory Qty: 4424; LED: BLUE; Manufacturer: ROHM; Manufacturer PN: SML-E12P8WT86; PART_NUMBER: 270-0176; Package Type: 0603
DB19 = LED: LED,GREEN,DIFFUSED,0603; 1ST PART FIELD: OUT19B; CLASS: DISCRETE; Inventory Qty: 4424; LED: BLUE; Manufacturer: ROHM; Manufacturer PN: SML-E12P8WT86; PART_NUMBER: 270-0176; Package Type: 0603
DB20 = LED: LED,GREEN,DIFFUSED,0603; 1ST PART FIELD: OUT20B; CLASS: DISCRETE; Inventory Qty: 4424; LED: BLUE; Manufacturer: ROHM; Manufacturer PN: SML-E12P8WT86; PART_NUMBER: 270-0176; Package Type: 0603
DB21 = LED: LED,GREEN,DIFFUSED,0603; 1ST PART FIELD: OUT21B; CLASS: DISCRETE; Inventory Qty: 4424; LED: BLUE; Manufacturer: ROHM; Manufacturer PN: SML-E12P8WT86; PART_NUMBER: 270-0176; Package Type: 0603
DB22 = LED: LED,GREEN,DIFFUSED,0603; 1ST PART FIELD: OUT22B; CLASS: DISCRETE; Inventory Qty: 4424; LED: BLUE; Manufacturer: ROHM; Manufacturer PN: SML-E12P8WT86; PART_NUMBER: 270-0176; Package Type: 0603
DB23 = LED: LED,GREEN,DIFFUSED,0603; 1ST PART FIELD: OUT23B; CLASS: DISCRETE; Inventory Qty: 4424; LED: BLUE; Manufacturer: ROHM; Manufacturer PN: SML-E12P8WT86; PART_NUMBER: 270-0176; Package Type: 0603
DB24 = LED: LED,GREEN,DIFFUSED,0603; 1ST PART FIELD: OUT24B; CLASS: DISCRETE; Inventory Qty: 4424; LED: BLUE; Manufacturer: ROHM; Manufacturer PN: SML-E12P8WT86; PART_NUMBER: 270-0176; Package Type: 0603
E71-E94 = MP-PINNED: TEST POINT,SILVER PLATE,PHOSPHOR BRONZE,3.81x2.03mm,2.29mm H,SMT; CLASS: DISCRETE; COMPFIXED: POS; Inventory Qty: 40128; Manufacturer: KEYSTONE; Manufacturer PN: 5019; PART_NUMBER: 260-0018; Package Size: 0.15" L x 0.080" W; Part Number: KEYSTONE-5019
QD43 QD48 QL25-QL42 QL44-QL47 = 3P_P-CH_TYPE1A: XSTR.,MOSFET,P-CH,100V,75mA,SOT-23-3; CLASS: DISCRETE; FPLIST: SOT23-3N,SOT23-3L,SOT23-3M; Inventory Qty: 10248; Manufacturer: DIODES INC.; Manufacturer PN: ZVP3310FTA; PART_NUMBER: 240-0366; Package Type: SOT-23-3; Rated Voltage: 100V
RD25-RD48 = RES: RES.,3M OHMS,1%,1/10W,0603; 1ST PART FIELD: 1%; CLASS: DISCRETE; FPLIST: CR0603N,CR0603L,CR0603M; Inventory Qty: 20000; Manufacturer: VISHAY; Manufacturer PN: CRCW06033M00FKEA; PART_NUMBER: 100-0479; Package Size: 0603; Part Number: ACC  CR16-914JM; Rated Power: 1/10W; Temperature Coefficient: 100ppm; Tolerance: 1%
RE25-RE48 = RES: RES.,6.2M OHMS,1%,1/10W,0603,AEC-Q200; CLASS: DISCRETE; FPLIST: CR0603N,CR0603L,CR0603M; Inventory Qty: 0; Manufacturer: VISHAY; Manufacturer PN: CRCW06036M20FKEA; PART_NUMBER: 100-1862; Package Size: 0603; Rated Power: 1/10W; Temperature Coefficient: +/-100ppm; Tolerance: 1%
RL25-RL48 = RES: RES.,20k OHMS,1%,1/4W,1206,AEC-Q200; 4TH PART FIELD: VISHAY,; CLASS: DISCRETE; FPLIST: CR1206N,CR1206L,CR1206M; Inventory Qty: 28804; Manufacturer: PANASONIC; Manufacturer PN: ERJ8ENF2002V; PART_NUMBER: 100-0607; Package Size: 1206; Rated Power: 1/4W; Temperature Coefficient: 100PPM; Tolerance: 1%
LB1 = BLANK_LABEL: LABEL SPEC, DEMO BOARD SERIAL NUMBER; Inventory Qty: 0; Manufacturer: BRADY; Manufacturer PN: THT-96-717-10; PART_FIELD_01: BOARD S/N LABEL; PART_NUMBER: 895-0154
MP1-MP9 = BLANK_MECHANICAL_PART: STANDOFF,NYLON,SNAP-ON,0.75" (19.1mm); CLASS: DISCRETE; FPLIST: KEYSTONE_8829-8834,KEYSTONE_8831,MTG-8831; Inventory Qty: 884; Manufacturer: WURTH ELEKTRONIK; Manufacturer PN: 702937000; PART_NUMBER: 763-0030
PCB1 = BLANK_PCB_PART: BOM Notes: REV03; CLASS: DISCRETE; Inventory Qty: 0; Manufacturer: ADI APPROVED SUPPLIER; Manufacturer PN: 600-DC3017A-B; PART_NUMBER: 600-DC3017A-B
PK1-PK3 = BLANK_MECHANICAL_PART: CONN.,POLARIZING KEY,PLUG,2.54mm PITCH,3.18mm DIM,ST,NATURAL THERMOPLASTIC; CLASS: CONNECTOR; Inventory Qty: 314; Manufacturer: SAMTEC; Manufacturer PN: PK-01-07; PART_NUMBER: 250-0122
J3 J4 = RJ45-SS-73100-046F: CONN.,MOD,STACKJACK,12PORTS(2x6),8P8C,R/A,THT,RJ45,ETHERNET,SHIELDED,50u" Au; CLASS: IO; Inventory Qty: 620; Manufacturer: STEWART CONN./ BEL; Manufacturer PN: SS73100-046F; PART_NUMBER: 250-0961
CA9-CA24 = CAP: CAP.,1000pF,X7R,2000V,10%,1808; CLASS: DISCRETE; Case Size: 1808; Dielectric Type: X7R; FPLIST: CC1808N,CC1808L,CC1808M; Inventory Qty: 13522; Manufacturer: KEMET; Manufacturer PN: C1808C102KGRACTU; PART_NUMBER: 150-3301; Package Size: 1808; Rated Voltage: 2000V; Tolerance: 10%
CB9-CB24 = CAP: CAP.,1000pF,X7R,2000V,10%,1808; CLASS: DISCRETE; Dielectric Type: X7R; FPLIST: CC1808N,CC1808L,CC1808M; Inventory Qty: 13522; Manufacturer: KEMET; Manufacturer PN: C1808C102KGRACTU; PART_NUMBER: 150-3301; Package Size: 1808; Rated Voltage: 2000V; Tolerance: 10%
CW9-CW24 CX9-CX24 CY9-CY24 CZ9-CZ24 = CAP: CAP.,0.01uF,X7R,100V,10%,0805; 1ST PART FIELD: 0805; CLASS: DISCRETE; Dielectric Type: X7R; FPLIST: CC0805N,CC0805L,CC0805M; Inventory Qty: 51316; Manufacturer: AVX; Manufacturer PN: 08051C103KAT2A; PART_NUMBER: 150-2308; Package Size: 0805; Package Type: SMD; Part Number: AVX 0805C103JAT2A; Rated Voltage: 100V; Tolerance: 10%; VOLTAGE: 100V
RO9-RO24 RP9-RP24 RQ9-RQ24 RR9-RR24 RW9-RW24 RX9-RX24 RY9-RY24 RZ9-RZ24 = RES: RES.,75 OHMS,5%,1/10W,0603,AEC-Q200; CLASS: DISCRETE; FPLIST: CR0603N,CR0603L,CR0603M; Inventory Qty: 64896; Manufacturer: NIC; Manufacturer PN: NRC06J750TRF; PART_NUMBER: 100-0315; Package Size: 0603; Part Number: VISHAY CRCW060375R0JNEA; Rated Power: 1/10W; Temperature Coefficient: 200ppm/C; Tolerance: 5%
RZZ33-RZZ40 RZZ45-RZZ100 = RES: RES.,0 OHM,1/10W,0603,AEC-Q200; CLASS: DISCRETE; FPLIST: CR0603N,CR0603L,CR0603M; Inventory Qty: 676258; Manufacturer: VISHAY; Manufacturer PN: CRCW06030000Z0EA; PART_NUMBER: 100-0009; Package Size: 0603; Part Number: VISHAY CRCW060375R0JNEA; Rated Power: 1/10W
T9-T12 = 7490220122: XFMR,LAN,1CT:1CT Tx, 1CT:1CT Rx,350uH,SMD,1000 Base-T,4PPoE,1 PORT; CLASS: DISCRETE; Inventory Qty: 1124; Manufacturer: WURTH ELEKTRONIK; PART_NUMBER: 410-0123; Part Number: MIDCOM WURTH 749022016; Turns Ratio: 1CT:1CT Tx, 1CT:1CT Rx
T13-T24 = WURTH-7490220122: XFMR,LAN,1CT:1CT Tx, 1CT:1CT Rx,350uH,SMD,1000 Base-T,4PPoE,1 PORT; CLASS: DISCRETE; Inventory Qty: 1124; Manufacturer: WURTH ELEKTRONIK; PART_NUMBER: 410-0123; Turns Ratio: 1CT:1CT Tx, 1CT:1CT Rx

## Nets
Agnd: QD43.2(S) QD48.2(S) QL25.2(S) QL26.2(S) QL27.2(S) QL28.2(S) QL29.2(S) QL30.2(S) QL31.2(S) QL32.2(S) QL33.2(S) QL34.2(S) QL35.2(S) QL36.2(S) QL37.2(S) QL38.2(S) QL39.2(S) QL40.2(S) QL41.2(S) QL42.2(S) QL44.2(S) QL45.2(S) QL46.2(S) QL47.2(S) RD25.1 RD26.1 RD27.1 RD28.1 RD29.1 RD30.1 RD31.1 RD32.1 RD33.1 RD34.1 RD35.1 RD36.1 RD37.1 RD38.1 RD39.1 RD40.1 RD41.1 RD42.1 RD43.1 RD44.1 RD45.1 RD46.1 RD47.1 RD48.1 RZZ34.2 RZZ36.2 RZZ39.2 RZZ40.2 RZZ47.2 RZZ48.2 RZZ49.2 RZZ51.2 RZZ53.2 RZZ55.2 RZZ57.2 RZZ59.2 RZZ61.2 RZZ62.2 RZZ65.2 RZZ66.2 RZZ69.2 RZZ70.2 RZZ73.2 RZZ74.2 RZZ77.2 RZZ78.2 RZZ81.2 RZZ82.2 RZZ85.2 RZZ86.2 RZZ89.2 RZZ90.2 RZZ93.2 RZZ94.2 RZZ97.2 RZZ98.2 ; also on sheet 1 2 3 4 5 12
VEE: DA13.1(CATHODE) DA14.1(CATHODE) DA15.1(CATHODE) DA16.1(CATHODE) DA17.1(CATHODE) DA18.1(CATHODE) DA19.1(CATHODE) DA20.1(CATHODE) DA21.1(CATHODE) DA22.1(CATHODE) DA23.1(CATHODE) DA24.1(CATHODE) DB13.1(CATHODE) DB14.1(CATHODE) DB15.1(CATHODE) DB16.1(CATHODE) DB17.1(CATHODE) DB18.1(CATHODE) DB19.1(CATHODE) DB20.1(CATHODE) DB21.1(CATHODE) DB22.1(CATHODE) DB23.1(CATHODE) DB24.1(CATHODE) ; also on sheet 1 2 3 4 12
CGND: CA9.2 CA10.2 CA11.2 CA12.2 CA13.2 CA14.2 CA15.2 CA16.2 CA17.2 CA18.2 CA19.2 CA20.2 CA21.2 CA22.2 CA23.2 CA24.2 CB9.2 CB10.2 CB11.2 CB12.2 CB13.2 CB14.2 CB15.2 CB16.2 CB17.2 CB18.2 CB19.2 CB20.2 CB21.2 CB22.2 CB23.2 CB24.2 J3.121 J3.122 J3.123 J3.127 J3.128 J3.129 ; also on sheet 1 4 5
OUT17: RZZ35.2 ; also on sheet 3 12
OUT18: RZZ33.2 ; also on sheet 3 12
OUT19: RZZ38.2 ; also on sheet 3 12
OUT20: RZZ37.2 ; also on sheet 3 12
OUT21: RZZ52.2 ; also on sheet 3 12
OUT22: RZZ50.2 ; also on sheet 3 12
OUT23: RZZ46.2 ; also on sheet 3 12
OUT24: RZZ45.2 ; also on sheet 3 12
OUT25: E78.1 RE25.1 RZZ60.2 ; also on sheet 3
OUT26: E94.1 RE26.1 RZZ58.2 ; also on sheet 3
OUT27: E72.1 RE27.1 RZZ56.2 ; also on sheet 3
OUT28: E80.1 RE28.1 RZZ54.2 ; also on sheet 3
OUT29: E93.1 RE29.1 RZZ64.2 ; also on sheet 3
OUT30: E77.1 RE30.1 RZZ63.2 ; also on sheet 3
OUT31: E90.1 RE31.1 RZZ68.2 ; also on sheet 3
OUT32: E81.1 RE32.1 RZZ67.2 ; also on sheet 3
OUT33: E84.1 RE33.1 RZZ76.2 ; also on sheet 3
OUT34: E79.1 RE34.1 RZZ75.2 ; also on sheet 3
OUT35: E89.1 RE35.1 RZZ72.2 ; also on sheet 3
OUT36: E87.1 RE36.1 RZZ71.2 ; also on sheet 3
OUT37: E85.1 RE37.1 RZZ80.2 ; also on sheet 3
OUT38: E92.1 RE38.1 RZZ79.2 ; also on sheet 3
OUT39: E88.1 RE39.1 RZZ84.2 ; also on sheet 3
OUT40: E71.1 RE40.1 RZZ83.2 ; also on sheet 3
OUT41: E76.1 RE41.1 RZZ92.2 ; also on sheet 3
OUT42: E91.1 RE42.1 RZZ91.2 ; also on sheet 3
OUT43: E82.1 RE43.1 RZZ88.2 ; also on sheet 3
OUT44: E75.1 RE44.1 RZZ87.2 ; also on sheet 3
OUT45: E83.1 RE45.1 RZZ96.2 ; also on sheet 3
OUT46: E74.1 RE46.1 RZZ95.2 ; also on sheet 3
OUT47: E86.1 RE47.1 RZZ100.2 ; also on sheet 3
OUT48: E73.1 RE48.1 RZZ99.2 ; also on sheet 3
N20490041: J4.1 T11.13(X-_D)
N20490047: J4.2 T11.14(X+_D)
N20490055: J4.3 T11.16(X-_C)
N20490066: J4.6 T11.17(X+_C)
N20490080: CB11.1 CW11.2 CX11.2 CY11.2 CZ11.2
N20490118: RO11.1 T11.10(TD_D)
N20490120: RP11.1 T11.7(TD_C)
N20490122: RQ11.1 T11.4(TD_B)
N20490132: RR11.1 T11.1(TD_A)
N20490138: RZ11.2 RZZ50.1 T11.24(TX_A)
N20490140: J4.8 T11.23(X+_A)
N20490144: J4.5 T11.20(X+_B)
N20490176: J4.7 T11.22(X-_A)
N20490178: RY11.2 RZZ49.1 T11.21(TX_B)
N20490211: CW11.1 RW11.1
N20490213: CY11.1 RY11.1
N20490215: CX11.1 RX11.1
N20490217: CZ11.1 RZ11.1
N20490219: CA11.1 RO11.2 RP11.2 RQ11.2 RR11.2
N20490221: RW11.2 RZZ52.1 T11.15(TX_D)
N20490225: RX11.2 RZZ51.1 T11.18(TX_C)
N20490311: J4.4 T11.19(X-_B)
N20490420: J4.21 T9.13(X-_D)
N20490426: J4.22 T9.14(X+_D)
N20490442: J4.23 T9.16(X-_C)
N20490461: J4.26 T9.17(X+_C)
N20490467: CB9.1 CW9.2 CX9.2 CY9.2 CZ9.2
N20490505: RO9.1 T9.10(TD_D)
N20490507: RP9.1 T9.7(TD_C)
N20490509: RQ9.1 T9.4(TD_B)
N20490519: RR9.1 T9.1(TD_A)
N20490525: RZ9.2 RZZ33.1 T9.24(TX_A)
N20490527: J4.28 T9.23(X+_A)
N20490539: J4.25 T9.20(X+_B)
N20490574: J4.27 T9.22(X-_A)
N20490576: RY9.2 RZZ34.1 T9.21(TX_B)
N20490590: CW9.1 RW9.1
N20490592: CY9.1 RY9.1
N20490594: CX9.1 RX9.1
N20490596: CZ9.1 RZ9.1
N20490598: CA9.1 RO9.2 RP9.2 RQ9.2 RR9.2
N20490602: RW9.2 RZZ35.1 T9.15(TX_D)
N20490606: RX9.2 RZZ36.1 T9.18(TX_C)
N20490696: J4.24 T9.19(X-_B)
N20490808: J4.12 T12.14(X+_D)
N20490812: J4.11 T12.13(X-_D)
N20490828: J4.13 T12.16(X-_C)
N20490843: J4.16 T12.17(X+_C)
N20490859: CB12.1 CW12.2 CX12.2 CY12.2 CZ12.2
N20490885: RQ12.1 T12.4(TD_B)
N20490887: RP12.1 T12.7(TD_C)
N20490889: RO12.1 T12.10(TD_D)
N20490901: J4.18 T12.23(X+_A)
N20490903: RZ12.2 RZZ45.1 T12.24(TX_A)
N20490909: RR12.1 T12.1(TD_A)
N20490923: J4.15 T12.20(X+_B)
N20490953: RY12.2 RZZ47.1 T12.21(TX_B)
N20490955: J4.17 T12.22(X-_A)
N20490957: CY12.1 RY12.1
N20490970: CW12.1 RW12.1
N20490986: CA12.1 RO12.2 RP12.2 RQ12.2 RR12.2
N20490988: RX12.2 RZZ48.1 T12.18(TX_C)
N20490992: RW12.2 RZZ46.1 T12.15(TX_D)
N20490996: CZ12.1 RZ12.1
N20490998: CX12.1 RX12.1
N20491088: J4.14 T12.19(X-_B)
N20491183: J4.31 T10.13(X-_D)
N20491189: J4.32 T10.14(X+_D)
N20491197: J4.33 T10.16(X-_C)
N20491216: J4.36 T10.17(X+_C)
N20491230: CB10.1 CW10.2 CX10.2 CY10.2 CZ10.2
N20491260: RO10.1 T10.10(TD_D)
N20491262: RP10.1 T10.7(TD_C)
N20491264: RQ10.1 T10.4(TD_B)
N20491274: RR10.1 T10.1(TD_A)
N20491280: RZ10.2 RZZ37.1 T10.24(TX_A)
N20491282: J4.38 T10.23(X+_A)
N20491294: J4.35 T10.20(X+_B)
N20491326: J4.37 T10.22(X-_A)
N20491328: RY10.2 RZZ39.1 T10.21(TX_B)
N20491353: CW10.1 RW10.1
N20491355: CY10.1 RY10.1
N20491357: CX10.1 RX10.1
N20491359: CZ10.1 RZ10.1
N20491361: CA10.1 RO10.2 RP10.2 RQ10.2 RR10.2
N20491363: RW10.2 RZZ38.1 T10.15(TX_D)
N20491367: RX10.2 RZZ40.1 T10.18(TX_C)
N20491453: J4.34 T10.19(X-_B)
N21989277: J3.81 T15.13(X-_D)
N21989280: J3.82 T15.14(X+_D)
N21989284: J3.83 T15.16(X-_C)
N21989285: J3.86 T15.17(X+_C)
N21989288: CB15.1 CW15.2 CX15.2 CY15.2 CZ15.2
N21989289: RO15.1 T15.10(TD_D)
N21989290: RP15.1 T15.7(TD_C)
N21989291: RQ15.1 T15.4(TD_B)
N21989292: RR15.1 T15.1(TD_A)
N21989295: RZ15.2 RZZ63.1 T15.24(TX_A)
N21989296: J3.88 T15.23(X+_A)
N21989297: J3.85 T15.20(X+_B)
N21989303: J3.87 T15.22(X-_A)
N21989304: RY15.2 RZZ61.1 T15.21(TX_B)
N21989311: CW15.1 RW15.1
N21989312: CY15.1 RY15.1
N21989313: CX15.1 RX15.1
N21989314: CZ15.1 RZ15.1
N21989315: CA15.1 RO15.2 RP15.2 RQ15.2 RR15.2
N21989316: RW15.2 RZZ64.1 T15.15(TX_D)
N21989318: RX15.2 RZZ62.1 T15.18(TX_C)
N21989328: J3.84 T15.19(X-_B)
N21989355: J3.101 T13.13(X-_D)
N21989358: J3.102 T13.14(X+_D)
N21989362: J3.103 T13.16(X-_C)
N21989363: J3.106 T13.17(X+_C)
N21989365: CB13.1 CW13.2 CX13.2 CY13.2 CZ13.2
N21989366: RO13.1 T13.10(TD_D)
N21989367: RP13.1 T13.7(TD_C)
N21989368: RQ13.1 T13.4(TD_B)
N21989369: RR13.1 T13.1(TD_A)
N21989372: RZ13.2 RZZ58.1 T13.24(TX_A)
N21989373: J3.108 T13.23(X+_A)
N21989374: J3.105 T13.20(X+_B)
N21989380: J3.107 T13.22(X-_A)
N21989381: RY13.2 RZZ57.1 T13.21(TX_B)
N21989388: CW13.1 RW13.1
N21989389: CY13.1 RY13.1
N21989390: CX13.1 RX13.1
N21989391: CZ13.1 RZ13.1
N21989392: CA13.1 RO13.2 RP13.2 RQ13.2 RR13.2
N21989393: RW13.2 RZZ60.1 T13.15(TX_D)
N21989395: RX13.2 RZZ59.1 T13.18(TX_C)
N21989405: J3.104 T13.19(X-_B)
N21989429: J3.92 T16.14(X+_D)
N21989431: J3.91 T16.13(X-_D)
N21989435: J3.93 T16.16(X-_C)
N21989438: J3.96 T16.17(X+_C)
N21989441: CB16.1 CW16.2 CX16.2 CY16.2 CZ16.2
N21989442: RQ16.1 T16.4(TD_B)
N21989443: RP16.1 T16.7(TD_C)
N21989444: RO16.1 T16.10(TD_D)
N21989445: J3.98 T16.23(X+_A)
N21989446: RZ16.2 RZZ67.1 T16.24(TX_A)
N21989449: RR16.1 T16.1(TD_A)
N21989451: J3.95 T16.20(X+_B)
N21989456: RY16.2 RZZ65.1 T16.21(TX_B)
N21989457: J3.97 T16.22(X-_A)
N21989458: CY16.1 RY16.1
N21989459: CW16.1 RW16.1
N21989466: CA16.1 RO16.2 RP16.2 RQ16.2 RR16.2
N21989467: RX16.2 RZZ66.1 T16.18(TX_C)
N21989469: RW16.2 RZZ68.1 T16.15(TX_D)
N21989471: CZ16.1 RZ16.1
N21989472: CX16.1 RX16.1
N21989484: J3.94 T16.19(X-_B)
N21989508: J3.111 T14.13(X-_D)
N21989511: J3.112 T14.14(X+_D)
N21989515: J3.113 T14.16(X-_C)
N21989516: J3.116 T14.17(X+_C)
N21989519: CB14.1 CW14.2 CX14.2 CY14.2 CZ14.2
N21989520: RO14.1 T14.10(TD_D)
N21989521: RP14.1 T14.7(TD_C)
N21989522: RQ14.1 T14.4(TD_B)
N21989523: RR14.1 T14.1(TD_A)
N21989526: RZ14.2 RZZ54.1 T14.24(TX_A)
N21989527: J3.118 T14.23(X+_A)
N21989528: J3.115 T14.20(X+_B)
N21989534: J3.117 T14.22(X-_A)
N21989535: RY14.2 RZZ53.1 T14.21(TX_B)
N21989542: CW14.1 RW14.1
N21989543: CY14.1 RY14.1
N21989544: CX14.1 RX14.1
N21989545: CZ14.1 RZ14.1
N21989546: CA14.1 RO14.2 RP14.2 RQ14.2 RR14.2
N21989547: RW14.2 RZZ56.1 T14.15(TX_D)
N21989549: RX14.2 RZZ55.1 T14.18(TX_C)
N21989559: J3.114 T14.19(X-_B)
N21992287: J3.41 T19.13(X-_D)
N21992290: J3.42 T19.14(X+_D)
N21992294: J3.43 T19.16(X-_C)
N21992295: J3.46 T19.17(X+_C)
N21992298: CB19.1 CW19.2 CX19.2 CY19.2 CZ19.2
N21992299: RO19.1 T19.10(TD_D)
N21992300: RP19.1 T19.7(TD_C)
N21992301: RQ19.1 T19.4(TD_B)
N21992302: RR19.1 T19.1(TD_A)
N21992305: RZ19.2 RZZ79.1 T19.24(TX_A)
N21992306: J3.48 T19.23(X+_A)
N21992307: J3.45 T19.20(X+_B)
N21992313: J3.47 T19.22(X-_A)
N21992314: RY19.2 RZZ77.1 T19.21(TX_B)
N21992321: CW19.1 RW19.1
N21992322: CY19.1 RY19.1
N21992323: CX19.1 RX19.1
N21992324: CZ19.1 RZ19.1
N21992325: CA19.1 RO19.2 RP19.2 RQ19.2 RR19.2
N21992326: RW19.2 RZZ80.1 T19.15(TX_D)
N21992328: RX19.2 RZZ78.1 T19.18(TX_C)
N21992338: J3.44 T19.19(X-_B)
N21992365: J3.61 T17.13(X-_D)
N21992368: J3.62 T17.14(X+_D)
N21992372: J3.63 T17.16(X-_C)
N21992373: J3.66 T17.17(X+_C)
N21992375: CB17.1 CW17.2 CX17.2 CY17.2 CZ17.2
N21992376: RO17.1 T17.10(TD_D)
N21992377: RP17.1 T17.7(TD_C)
N21992378: RQ17.1 T17.4(TD_B)
N21992379: RR17.1 T17.1(TD_A)
N21992382: RZ17.2 RZZ75.1 T17.24(TX_A)
N21992383: J3.68 T17.23(X+_A)
N21992384: J3.65 T17.20(X+_B)
N21992390: J3.67 T17.22(X-_A)
N21992391: RY17.2 RZZ73.1 T17.21(TX_B)
N21992398: CW17.1 RW17.1
N21992399: CY17.1 RY17.1
N21992400: CX17.1 RX17.1
N21992401: CZ17.1 RZ17.1
N21992402: CA17.1 RO17.2 RP17.2 RQ17.2 RR17.2
N21992403: RW17.2 RZZ76.1 T17.15(TX_D)
N21992405: RX17.2 RZZ74.1 T17.18(TX_C)
N21992415: J3.64 T17.19(X-_B)
N21992439: J3.52 T20.14(X+_D)
N21992441: J3.51 T20.13(X-_D)
N21992445: J3.53 T20.16(X-_C)
N21992448: J3.56 T20.17(X+_C)
N21992451: CB20.1 CW20.2 CX20.2 CY20.2 CZ20.2
N21992452: RQ20.1 T20.4(TD_B)
N21992453: RP20.1 T20.7(TD_C)
N21992454: RO20.1 T20.10(TD_D)
N21992455: J3.58 T20.23(X+_A)
N21992456: RZ20.2 RZZ83.1 T20.24(TX_A)
N21992459: RR20.1 T20.1(TD_A)
N21992461: J3.55 T20.20(X+_B)
N21992466: RY20.2 RZZ81.1 T20.21(TX_B)
N21992467: J3.57 T20.22(X-_A)
N21992468: CY20.1 RY20.1
N21992469: CW20.1 RW20.1
N21992476: CA20.1 RO20.2 RP20.2 RQ20.2 RR20.2
N21992477: RX20.2 RZZ82.1 T20.18(TX_C)
N21992479: RW20.2 RZZ84.1 T20.15(TX_D)
N21992481: CZ20.1 RZ20.1
N21992482: CX20.1 RX20.1
N21992494: J3.54 T20.19(X-_B)
N21992518: J3.71 T18.13(X-_D)
N21992521: J3.72 T18.14(X+_D)
N21992525: J3.73 T18.16(X-_C)
N21992526: J3.76 T18.17(X+_C)
N21992529: CB18.1 CW18.2 CX18.2 CY18.2 CZ18.2
N21992530: RO18.1 T18.10(TD_D)
N21992531: RP18.1 T18.7(TD_C)
N21992532: RQ18.1 T18.4(TD_B)
N21992533: RR18.1 T18.1(TD_A)
N21992536: RZ18.2 RZZ71.1 T18.24(TX_A)
N21992537: J3.78 T18.23(X+_A)
N21992538: J3.75 T18.20(X+_B)
N21992544: J3.77 T18.22(X-_A)
N21992545: RY18.2 RZZ69.1 T18.21(TX_B)
N21992552: CW18.1 RW18.1
N21992553: CY18.1 RY18.1
N21992554: CX18.1 RX18.1
N21992555: CZ18.1 RZ18.1
N21992556: CA18.1 RO18.2 RP18.2 RQ18.2 RR18.2
N21992557: RW18.2 RZZ72.1 T18.15(TX_D)
N21992559: RX18.2 RZZ70.1 T18.18(TX_C)
N21992569: J3.74 T18.19(X-_B)
N21994747: J3.1 T23.13(X-_D)
N21994750: J3.2 T23.14(X+_D)
N21994754: J3.3 T23.16(X-_C)
N21994755: J3.6 T23.17(X+_C)
N21994758: CB23.1 CW23.2 CX23.2 CY23.2 CZ23.2
N21994759: RO23.1 T23.10(TD_D)
N21994760: RP23.1 T23.7(TD_C)
N21994761: RQ23.1 T23.4(TD_B)
N21994762: RR23.1 T23.1(TD_A)
N21994765: RZ23.2 RZZ95.1 T23.24(TX_A)
N21994766: J3.8 T23.23(X+_A)
N21994767: J3.5 T23.20(X+_B)
N21994773: J3.7 T23.22(X-_A)
N21994774: RY23.2 RZZ93.1 T23.21(TX_B)
N21994781: CW23.1 RW23.1
N21994782: CY23.1 RY23.1
N21994783: CX23.1 RX23.1
N21994784: CZ23.1 RZ23.1
N21994785: CA23.1 RO23.2 RP23.2 RQ23.2 RR23.2
N21994786: RW23.2 RZZ96.1 T23.15(TX_D)
N21994788: RX23.2 RZZ94.1 T23.18(TX_C)
N21994798: J3.4 T23.19(X-_B)
N21994825: J3.21 T21.13(X-_D)
N21994828: J3.22 T21.14(X+_D)
N21994832: J3.23 T21.16(X-_C)
N21994833: J3.26 T21.17(X+_C)
N21994835: CB21.1 CW21.2 CX21.2 CY21.2 CZ21.2
N21994836: RO21.1 T21.10(TD_D)
N21994837: RP21.1 T21.7(TD_C)
N21994838: RQ21.1 T21.4(TD_B)
N21994839: RR21.1 T21.1(TD_A)
N21994842: RZ21.2 RZZ91.1 T21.24(TX_A)
N21994843: J3.28 T21.23(X+_A)
N21994844: J3.25 T21.20(X+_B)
N21994850: J3.27 T21.22(X-_A)
N21994851: RY21.2 RZZ89.1 T21.21(TX_B)
N21994858: CW21.1 RW21.1
N21994859: CY21.1 RY21.1
N21994860: CX21.1 RX21.1
N21994861: CZ21.1 RZ21.1
N21994862: CA21.1 RO21.2 RP21.2 RQ21.2 RR21.2
N21994863: RW21.2 RZZ92.1 T21.15(TX_D)
N21994865: RX21.2 RZZ90.1 T21.18(TX_C)
N21994875: J3.24 T21.19(X-_B)
N21994899: J3.12 T24.14(X+_D)
N21994901: J3.11 T24.13(X-_D)
N21994905: J3.13 T24.16(X-_C)
N21994908: J3.16 T24.17(X+_C)
N21994911: CB24.1 CW24.2 CX24.2 CY24.2 CZ24.2
N21994912: RQ24.1 T24.4(TD_B)
N21994913: RP24.1 T24.7(TD_C)
N21994914: RO24.1 T24.10(TD_D)
N21994915: J3.18 T24.23(X+_A)
N21994916: RZ24.2 RZZ99.1 T24.24(TX_A)
N21994919: RR24.1 T24.1(TD_A)
N21994921: J3.15 T24.20(X+_B)
N21994926: RY24.2 RZZ97.1 T24.21(TX_B)
N21994927: J3.17 T24.22(X-_A)
N21994928: CY24.1 RY24.1
N21994929: CW24.1 RW24.1
N21994936: CA24.1 RO24.2 RP24.2 RQ24.2 RR24.2
N21994937: RX24.2 RZZ98.1 T24.18(TX_C)
N21994939: RW24.2 RZZ100.1 T24.15(TX_D)
N21994941: CZ24.1 RZ24.1
N21994942: CX24.1 RX24.1
N21994954: J3.14 T24.19(X-_B)
N21994978: J3.31 T22.13(X-_D)
N21994981: J3.32 T22.14(X+_D)
N21994985: J3.33 T22.16(X-_C)
N21994986: J3.36 T22.17(X+_C)
N21994989: CB22.1 CW22.2 CX22.2 CY22.2 CZ22.2
N21994990: RO22.1 T22.10(TD_D)
N21994991: RP22.1 T22.7(TD_C)
N21994992: RQ22.1 T22.4(TD_B)
N21994993: RR22.1 T22.1(TD_A)
N21994996: RZ22.2 RZZ87.1 T22.24(TX_A)
N21994997: J3.38 T22.23(X+_A)
N21994998: J3.35 T22.20(X+_B)
N21995004: J3.37 T22.22(X-_A)
N21995005: RY22.2 RZZ85.1 T22.21(TX_B)
N21995012: CW22.1 RW22.1
N21995013: CY22.1 RY22.1
N21995014: CX22.1 RX22.1
N21995015: CZ22.1 RZ22.1
N21995016: CA22.1 RO22.2 RP22.2 RQ22.2 RR22.2
N21995017: RW22.2 RZZ88.1 T22.15(TX_D)
N21995019: RX22.2 RZZ86.1 T22.18(TX_C)
N21995029: J3.34 T22.19(X-_B)
N22072968: QL25.1(G) RD25.2 RE25.2
N22072973: QL26.1(G) RD26.2 RE26.2
N22072992: QL27.1(G) RD27.2 RE27.2
N22072999: QL28.1(G) RD28.2 RE28.2
N22073016: QL29.1(G) RD29.2 RE29.2
N22073021: QL30.1(G) RD30.2 RE30.2
N22073040: QL31.1(G) RD31.2 RE31.2
N22073045: QL32.1(G) RD32.2 RE32.2
N22073064: QL33.1(G) RD33.2 RE33.2
N22073069: QL34.1(G) RD34.2 RE34.2
N22073088: QL35.1(G) RD35.2 RE35.2
N22073093: QL36.1(G) RD36.2 RE36.2
N22073117: QL38.1(G) RD38.2 RE38.2
N22073136: QL39.1(G) RD39.2 RE39.2
N22073141: QL40.1(G) RD40.2 RE40.2
N22073160: QL41.1(G) RD41.2 RE41.2
N22073165: QL42.1(G) RD42.2 RE42.2
N22073184: QD43.1(G) RD43.2 RE43.2
N22073189: QL44.1(G) RD44.2 RE44.2
N22073208: QL45.1(G) RD45.2 RE45.2
N22073215: QL46.1(G) RD46.2 RE46.2
N22073232: QL47.1(G) RD47.2 RE47.2
N22073237: QD48.1(G) RD48.2 RE48.2
N23328040: QL37.1(G) RD37.2 RE37.2
N23329246: QL32.3(D) RL32.2
N23332062: QD43.3(D) RL43.2
N23332234: QL44.3(D) RL44.2
N23332557: QL34.3(D) RL34.2
N23332740: QL35.3(D) RL35.2
N23332904: QL36.3(D) RL36.2
N23333433: QL46.3(D) RL46.2
N23333598: QD48.3(D) RL48.2
N23333754: QL47.3(D) RL47.2
N23348147: QL25.3(D) RL25.2
N23348173: QL26.3(D) RL26.2
N23348261: QL27.3(D) RL27.2
N23348286: QL28.3(D) RL28.2
N23348377: DA13.2(ANODE) RL25.1
N23348383: DB13.2(ANODE) RL26.1
N23348389: DA14.2(ANODE) RL27.1
N23348395: DB14.2(ANODE) RL28.1
N23348546: QL31.3(D) RL31.2
N23348762: QL33.3(D) RL33.2
N23348981: DB18.2(ANODE) RL36.1
N23349030: QL37.3(D) RL37.2
N23349058: DA19.2(ANODE) RL37.1
N23349083: QL38.3(D) RL38.2
N23349111: DB19.2(ANODE) RL38.1
N23349191: QL39.3(D) RL39.2
N23349255: DA20.2(ANODE) RL39.1
N23349282: QL40.3(D) RL40.2
N23349312: DB20.2(ANODE) RL40.1
N23349348: QL41.3(D) RL41.2
N23349414: DA21.2(ANODE) RL41.1
N23349566: QL42.3(D) RL42.2
N23349572: DB21.2(ANODE) RL42.1
N23349696: DA22.2(ANODE) RL43.1
N23349817: DB22.2(ANODE) RL44.1
N23349878: QL45.3(D) RL45.2
N23349909: DA23.2(ANODE) RL45.1
N23350033: DB23.2(ANODE) RL46.1
N23350153: DA24.2(ANODE) RL47.1
N23350277: DB24.2(ANODE) RL48.1
N23351465: DA15.2(ANODE) RL29.1
N23351494: DB15.2(ANODE) RL30.1
N23351614: DA16.2(ANODE) RL31.1
N23351671: DB16.2(ANODE) RL32.1
N23351700: DA17.2(ANODE) RL33.1
N23351792: DB17.2(ANODE) RL34.1
N23351907: DA18.2(ANODE) RL35.1
N23607531: QL30.3(D) RL30.2
N23671726: QL29.3(D) RL29.2

Not connected (* = marked no-connect by the designer): J3 124* 125* 126*; T9 2(D+_A) 3(D-_A) 5(D+_B) 6(D-_B) 8(D+_C) 9(D-_C) 11(D+_D) 12(D-_D); T10 2(D+_A) 3(D-_A) 5(D+_B) 6(D-_B) 8(D+_C) 9(D-_C) 11(D+_D) 12(D-_D); T11 2(D+_A) 3(D-_A) 5(D+_B) 6(D-_B) 8(D+_C) 9(D-_C) 11(D+_D) 12(D-_D); T12 2(D+_A) 3(D-_A) 5(D+_B) 6(D-_B) 8(D+_C) 9(D-_C) 11(D+_D) 12(D-_D); T13 2(D+_A) 3(D-_A) 5(D+_B) 6(D-_B) 8(D+_C) 9(D-_C) 11(D+_D) 12(D-_D); T14 2(D+_A) 3(D-_A) 5(D+_B) 6(D-_B) 8(D+_C) 9(D-_C) 11(D+_D) 12(D-_D); T15 2(D+_A) 3(D-_A) 5(D+_B) 6(D-_B) 8(D+_C) 9(D-_C) 11(D+_D) 12(D-_D); T16 2(D+_A) 3(D-_A) 5(D+_B) 6(D-_B) 8(D+_C) 9(D-_C) 11(D+_D) 12(D-_D); T17 2(D+_A) 3(D-_A) 5(D+_B) 6(D-_B) 8(D+_C) 9(D-_C) 11(D+_D) 12(D-_D); T18 2(D+_A) 3(D-_A) 5(D+_B) 6(D-_B) 8(D+_C) 9(D-_C) 11(D+_D) 12(D-_D); T19 2(D+_A) 3(D-_A) 5(D+_B) 6(D-_B) 8(D+_C) 9(D-_C) 11(D+_D) 12(D-_D); T20 2(D+_A) 3(D-_A) 5(D+_B) 6(D-_B) 8(D+_C) 9(D-_C) 11(D+_D) 12(D-_D); T21 2(D+_A) 3(D-_A) 5(D+_B) 6(D-_B) 8(D+_C) 9(D-_C) 11(D+_D) 12(D-_D); T22 2(D+_A) 3(D-_A) 5(D+_B) 6(D-_B) 8(D+_C) 9(D-_C) 11(D+_D) 12(D-_D); T23 2(D+_A) 3(D-_A) 5(D+_B) 6(D-_B) 8(D+_C) 9(D-_C) 11(D+_D) 12(D-_D); T24 2(D+_A) 3(D-_A) 5(D+_B) 6(D-_B) 8(D+_C) 9(D-_C) 11(D+_D) 12(D-_D)

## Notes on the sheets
sheet 6
- PORTS 9 - 12
- REVISION HISTORY
- UPPER ROW
- ECO
- REV
- DESCRIPTION
- APPROVED
- DATE
- 3
- PoE OUT
- PoE OUT
- PORT 12
- PORT 10
- PoE OUT
- PoE OUT
- PORT 9
- PORT 11
- LOWER ROW
- NOTE: UNLESS OTHERWISE SPECIFIED
- 1.  ALL RESISTORS AND CAPACITORS ARE 0603.
- 2.  INSTALL SHUNTS AS SHOWN.
sheet 7
- REVISION HISTORY
- PORTS 13 - 16
- UPPER ROW
- ECO
- REV
- DESCRIPTION
- APPROVED
- DATE
- 3
- PoE OUT
- PoE OUT
- PORT 16
- PORT 14
- PoE OUT
- PoE OUT
- PORT 13
- PORT 15
- LOWER ROW
- NOTE: UNLESS OTHERWISE SPECIFIED
- 1.  ALL RESISTORS AND CAPACITORS ARE 0603.
- 2.  INSTALL SHUNTS AS SHOWN.
sheet 8
- REVISION HISTORY
- PORTS 17 - 20
- UPPER ROW
- ECO
- REV
- DESCRIPTION
- APPROVED
- DATE
- 3
- PoE OUT
- PoE OUT
- PORT 20
- PORT 18
- PoE OUT
- PoE OUT
- PORT 17
- PORT 19
- LOWER ROW
- NOTE: UNLESS OTHERWISE SPECIFIED
- 1.  ALL RESISTORS AND CAPACITORS ARE 0603.
- 2.  INSTALL SHUNTS AS SHOWN.
sheet 9
- REVISION HISTORY
- PORTS 21 - 24
- UPPER ROW
- ECO
- REV
- DESCRIPTION
- APPROVED
- DATE
- 3
- PoE OUT
- PoE OUT
- PORT 22
- PORT 24
- PoE OUT
- PoE OUT
- PORT 21
- PORT 23
- LOWER ROW
- NOTE: UNLESS OTHERWISE SPECIFIED
- 1.  ALL RESISTORS AND CAPACITORS ARE 0603.
- 2.  INSTALL SHUNTS AS SHOWN.
sheet 10
- HARDWARE
- PCA ADDITIONAL PARTS
- (MAO BANG)
- NOTE: UNLESS OTHERWISE SPECIFIED
- 1.  INSTALL SHUNTS AS SHOWN.
sheet 11
- REVISION HISTORY
- PORTS 13-24 LEDS
- ECO
- REV
- DESCRIPTION
- APPROVED
- DATE
- 3
- OPTIONAL PORT LED DRIVERS - PORTS 13 -18
- OPTIONAL PORT LED DRIVERS - PORTS 19 -24
- OUT13A
- OUT13B
- OUT14A
- OUT14B
- OUT19A
- OUT19A
- OUT19B
- OUT20A
- OUT20B
- OUT13A
- OUT13B
- OUT14A
- OUT14B
- OUT19B
- OUT20A
- OUT20B
- PORT 13
- PORT 14
- PORT 19
- PORT 20
- OUT15A
- OUT15B
- OUT16A
- OUT16B
- OUT21A
- OUT21B
- OUT22A
- OUT22B
- OUT15A
- OUT15B
- OUT16A
- OUT16B
- OUT21A
- OUT21B
- OUT22A
- OUT22B
- PORT 15
- PORT 16
- PORT 21
- PORT 22
- OUT17A
- OUT17B
- OUT18A
- OUT18B
- OUT23A
- OUT23B
- OUT24A
- OUT24B
- OUT17A
- OUT17B
- OUT18A
- OUT23A
- OUT23B
- OUT24A
- OUT24B
- OUT18B
- PORT 17
- PORT 18
- PORT 23
- PORT 24
- NOTE: UNLESS OTHERWISE SPECIFIED
- 1.  ALL RESISTORS AND CAPACITORS ARE 0603.
- 2.  INSTALL SHUNTS AS SHOWN.
